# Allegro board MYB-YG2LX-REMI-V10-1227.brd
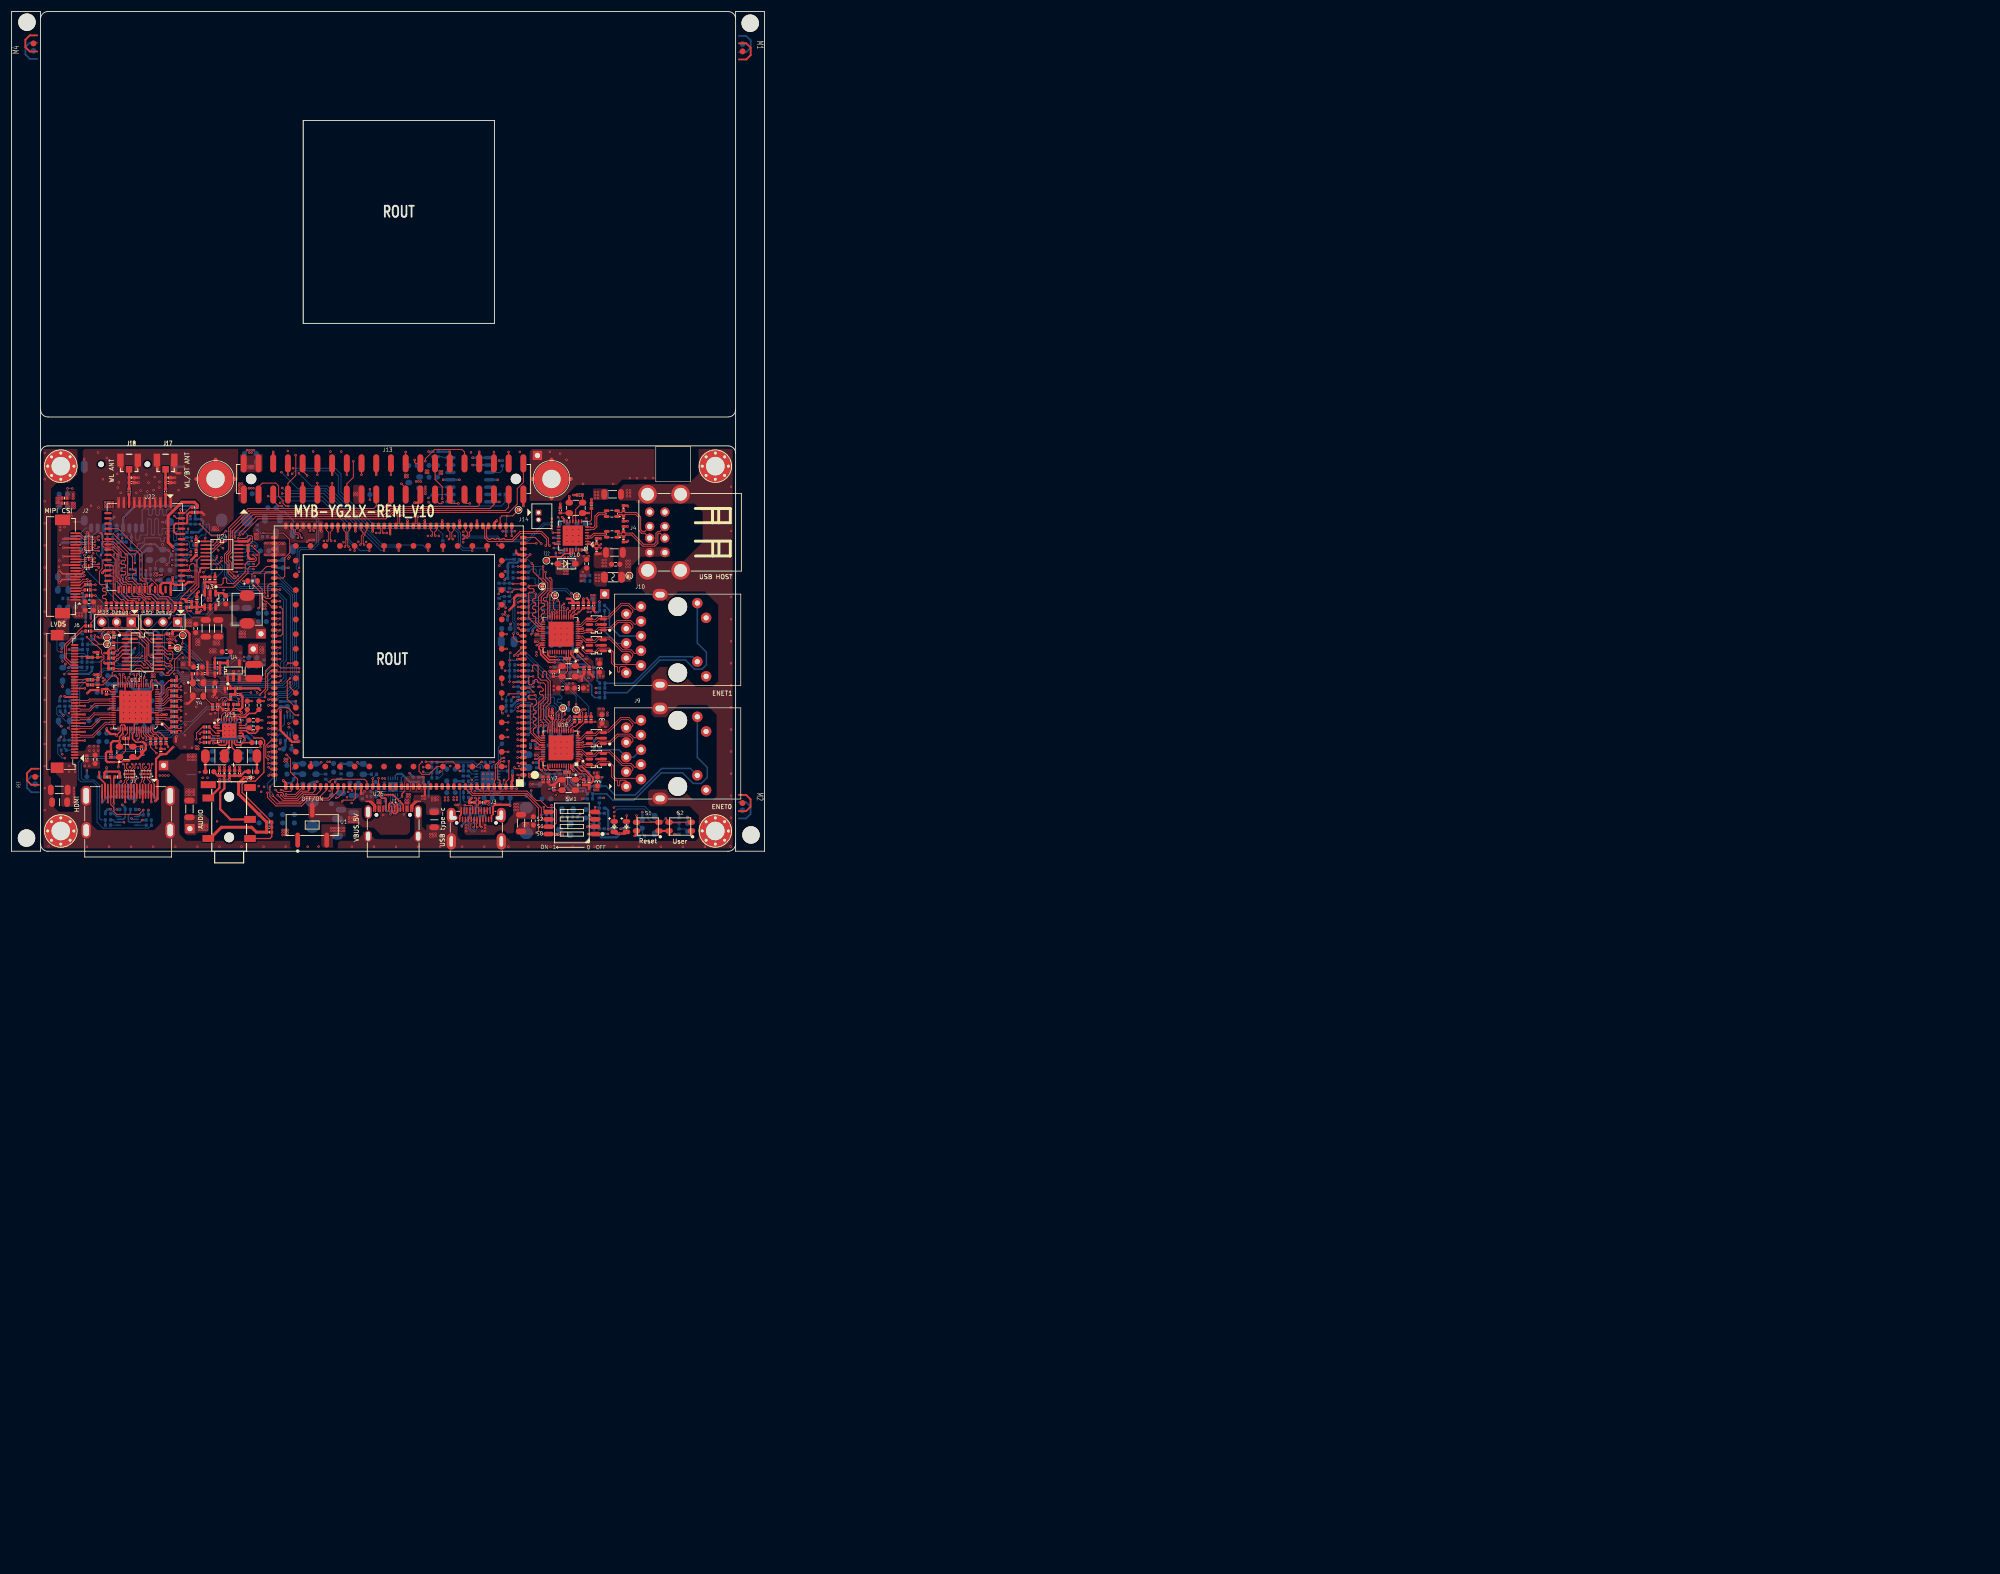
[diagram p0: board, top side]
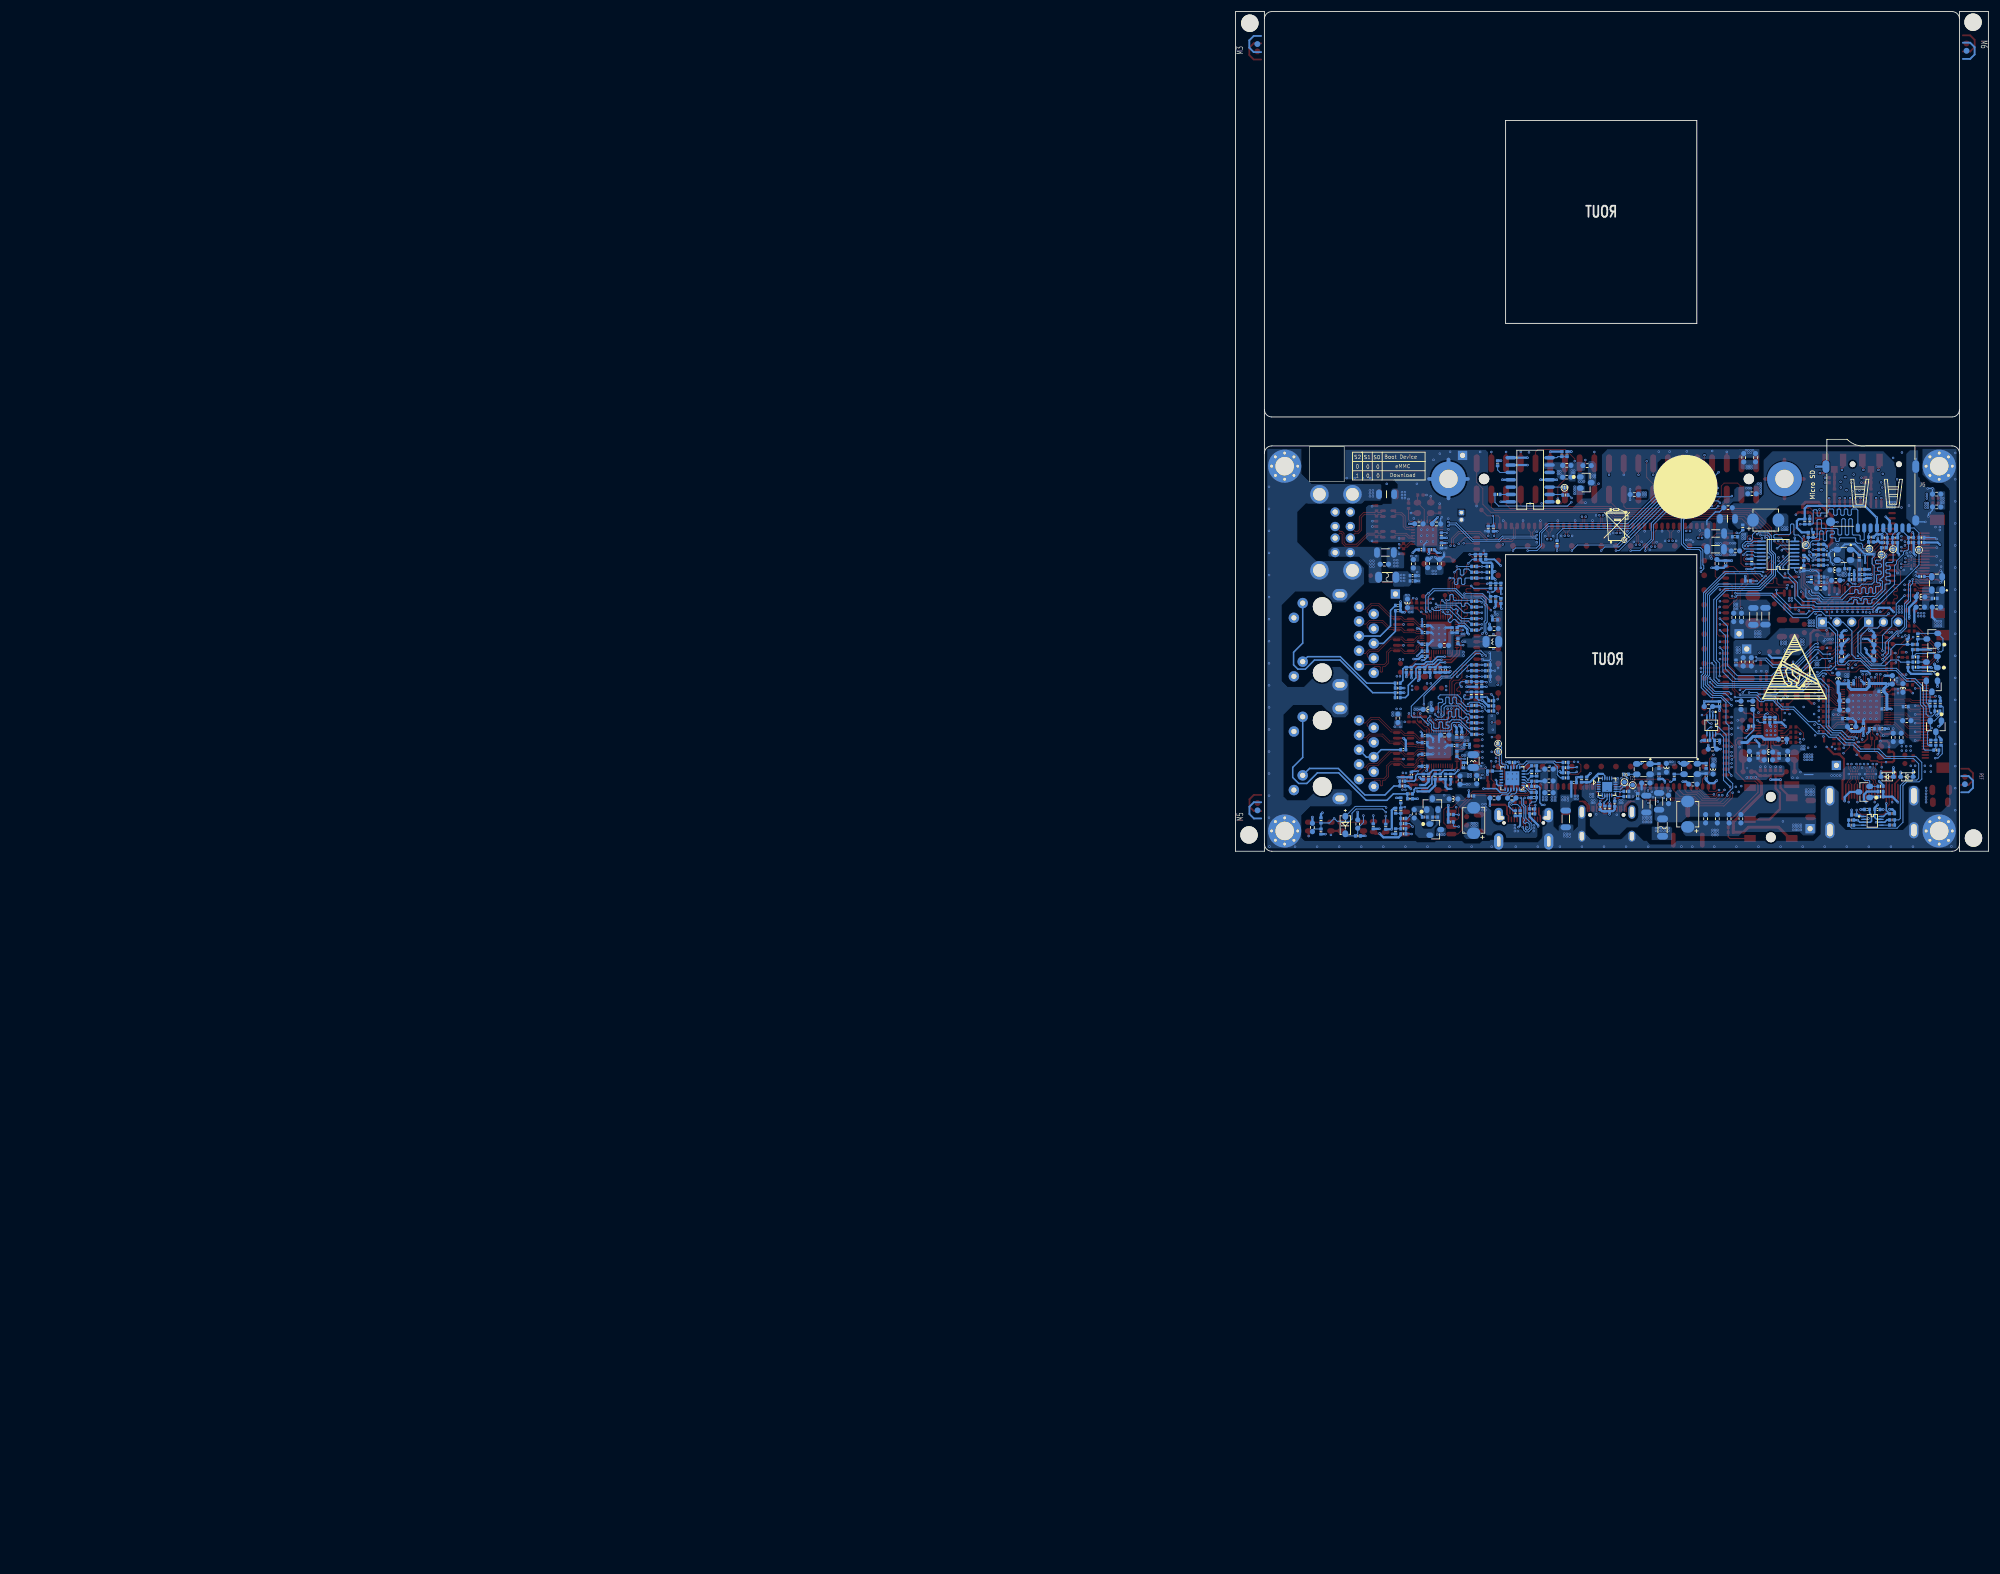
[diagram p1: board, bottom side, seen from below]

Outline 130 x 145 mm; copper layers: TOP, GND02, ART03, ART04, POW05, BOTTOM. Coordinates in mm from the lower left corner of the outline.
Outline path: 5,143.73 5,145 0,145 0,0 5,0 5,1.27 ; 5,143.73 5,76.27 ; 5,143.73 arc(5.37,144.63) 6.27,145 123.73,145 arc(124.63,144.63) 125,143.73 ; 5,76.27 5,68.73 ; 5,76.27 arc(5.37,75.37) 6.27,75 123.73,75 arc(124.63,75.37) 125,76.27 ; 5,68.73 arc(5.37,69.63) 6.27,70 123.73,70 arc(124.63,69.63) 125,68.73 ; 5,68.73 5,1.27 ; 5,1.27 arc(5.37,0.37) 6.27,0 123.73,0 arc(124.63,0.37) 125,1.27 ; 50.34,126.21 83.36,126.21 ; 50.34,126.21 83.36,126.21 ; 50.34,126.21 50.34,91.15 ; 50.34,126.21 50.34,91.15 ; 83.36,126.21 83.36,91.15 ; 83.36,126.21 83.36,91.15 ; 50.34,91.15 83.36,91.15 ; 50.34,91.15 83.36,91.15 ; 50.34,51.21 83.36,51.21 ; 50.34,51.21 83.36,51.21 ; 50.34,51.21 50.34,16.15 ; 50.34,51.21 50.34,16.15 ; 83.36,51.21 83.36,16.15 ; 83.36,51.21 83.36,16.15 ; 50.34,16.15 83.36,16.15 ; 50.34,16.15 83.36,16.15 ; 125,143.73 125,145 130,145 130,0 125,0 125,1.27 ; 125,143.73 125,76.27 ; 125,68.73 125,76.27 ; 125,68.73 125,1.27

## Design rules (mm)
net group AUDIO_MCLK: nets AUDIO_MCLK N26081482
net group DIFFPAIR0: nets RZ_USB0_DM RZ_USB0_DP
net group DIFFPAIR1: nets N26155524 N26155536
net group DIFFPAIR2: nets N26155544 N26155546
net group DPCSI_CLK_: nets CSI_CLK_N CSI_CLK_P
net group DPCSI_DATA0_: nets CSI_DATA0_N CSI_DATA0_P
net group DPCSI_DATA1_: nets CSI_DATA1_N CSI_DATA1_P
net group DPCSI_DATA2_: nets CSI_DATA2_N CSI_DATA2_P
net group DPCSI_DATA3_: nets CSI_DATA3_N CSI_DATA3_P
net group ET0_LINKSTA: nets ET0_LINKSTA N26048526
net group ET0_RX_CTL: nets ET0_RX_CTL N24791040
net group ET0_RXC: nets ET0_RXC N24696137
net group ET0_RXD0: nets ET0_RXD0 N24696102
net group ET0_RXD1: nets ET0_RXD1 N24696123
net group ET0_RXD2: nets ET0_RXD2 N24696121
net group ET0_RXD3: nets ET0_RXD3 N24696119
net group ET0_TX_CTL: nets ET0_TX_CTL N24790962
net group ET0_TXC: nets ET0_TXC N24696861
net group ET0_TXD1: nets ET0_TXD1 N24696875
net group ET0_TXD2: nets ET0_TXD2 N24696883
net group ET0_TXD3: nets ET0_TXD3 N24696881
net group ET1_RX_CTL: nets ET1_RX_CTL N24806933
net group ET1_RXD0: nets ET1_RXD0 N24807160
net group ET1_TX_CTL: nets ET1_TX_CTL N24806931
net group ET1_TXD0: nets ET1_TXD0 N24807847
net group ET1_TXD1: nets ET1_TXD1 N24807859
net group ET1_TXD2: nets ET1_TXD2 N24807879
net group ET1_TXD3: nets ET1_TXD3 N24807877
net group HOST1_USB: nets HOST1_USB_DM HOST1_USB_DP
net group HOST2_USB: nets HOST2_USB_DM HOST2_USB_DP
net group HPD_DET: nets HPD_DET N24681971
net group INT: nets INT RZ_P16_1_1V8
net group N23726017: nets N23726017 N23737816
net group N24759067: nets N24759067 N24761427
net group N24806528: nets N24806528 N24806541
net group RZ_DSI_CLK_N: nets N25318611 RZ_DSI_CLK_N
net group RZ_DSI_DATA0_N: nets N25318514 RZ_DSI_DATA0_N
net group RZ_DSI_DATA2_P: nets N25318630 RZ_DSI_DATA2_P
net group RZ_DSI_DATA3_N: nets N25318677 RZ_DSI_DATA3_N
net group RZ_P39_0_1V8: nets N23565746 RZ_P39_0_1V8
net group RZ_P42_2_1V8: nets N25318354 RZ_P42_2_1V8
net group RZ_P42_3: nets N25931062 RZ_P42_3
net group RZ_P43_0: nets N25931049 RZ_P43_0
net group RZ_P44_3: nets RZ_P44_2 RZ_P44_3
net group RZ_P48_2: nets N25931057 RZ_P48_2
net group RZ_SCIF1_CTS: nets RZ_SCIF1_CTS UART_CTS
net group RZ_SCIF1_RTS: nets RZ_SCIF1_RTS UART_RTS
net group RZ_SCIF1_RXD: nets N26045131 RZ_SCIF1_RXD
net group RZ_SCIF1_TXD: nets N26045129 RZ_SCIF1_TXD
net group RZ_SSI0_BCK: nets N26048225 RZ_SSI0_BCK
net group RZ_SSI0_RCK: nets N26048227 RZ_SSI0_RCK
net group RZ_SSI0_RXD: nets N26048711 RZ_SSI0_RXD
net group RZ_SSI0_TXD: nets N26048728 RZ_SSI0_TXD
net group RZ_USB1: nets RZ_USB1_DM RZ_USB1_DP
net group SDIO_CLK: nets SDIO_CLK WIFI_SD1_CLK
net group SDIO_CMD: nets SDIO_CMD WIFI_SD1_CMD
net group SDIO_DATA0: nets SDIO_DATA0 WIFI_SD1_D0
net group SDIO_DATA1: nets SDIO_DATA1 WIFI_SD1_D1
net group SDIO_DATA2: nets SDIO_DATA2 WIFI_SD1_D2
net group SDIO_DATA3: nets SDIO_DATA3 WIFI_SD1_D3
net group TX0__OUT: nets TX0_DN_OUT TX0_DP_OUT
net group TX1_OUT: nets TX1_DN_OUT TX1_DP_OUT
net group TX2_OUT: nets TX2_DN_OUT TX2_DP_OUT
net group TX_CK_OUT: nets TX_CKN_OUT TX_CKP_OUT
net group CARRIER_PWR_ON: nets CARRIER_PWR_ON N26033210 N26043190
net group DPTX: nets TX0_DN TX0_DP TX1_DN TX1_DP TX2_DN TX2_DP TX_CKN TX_CKP
net group ET1_RXD1: nets N24807181
net group ET1_RXD2: nets N24807179
net group ET1_RXD3: nets N24807177
net group ET1_TXC: nets ET1_TXC
net group LVDS: nets LVDS_CLK+ LVDS_CLK- LVDS_D0+ LVDS_D0- LVDS_D1+ LVDS_D1- LVDS_D2+ LVDS_D2- LVDS_D3+ LVDS_D3-
net group RGB: nets RZ_DISP_CLK RZ_DISP_DATA2 RZ_DISP_DATA5 RZ_DISP_DATA10 RZ_DISP_DATA11 RZ_DISP_DATA12 RZ_DISP_DATA13 RZ_DISP_DATA14 RZ_DISP_DATA15 RZ_DISP_DATA16 RZ_DISP_DATA17 RZ_DISP_DATA18 RZ_DISP_DATA19 RZ_DISP_DATA21 RZ_DISP_DE RZ_DISP_HSYNC RZ_DISP_VSYNC
net group RIIC0_SCL_1V8: nets N23563890 N25318324 RIIC0_SCL_1V8
net group RIIC0_SDA_1V8: nets N23563869 N25318297 RIIC0_SDA_1V8
net group RZ_CSI_DATA: nets RZ_CSI_CLK_N RZ_CSI_CLK_P RZ_CSI_DATA0_N RZ_CSI_DATA0_P RZ_CSI_DATA1_N RZ_CSI_DATA1_P RZ_CSI_DATA2_N RZ_CSI_DATA2_P RZ_CSI_DATA3_N RZ_CSI_DATA3_P
net group RZ_P43_3: nets RZ_P43_3
net group RZ_RIIC0_SCL: nets N25931055 N26059408 RZ_RIIC0_SCL
net group RZ_RIIC0_SDA: nets N25931053 N26059410 RZ_RIIC0_SDA
net group RZ_RIIC1_SCL: nets N23950839 N24683528 N26048238 RZ_RIIC1_SCL
net group RZ_RIIC1_SDA: nets N23950837 N24683530 N26048236 RZ_RIIC1_SDA
net group SD1_CLK: nets N24944194
net group USB2CC1: nets N26059354 N26059432 USB2CC1
net group USB2CC2: nets N26059364 N26059430 USB2CC2

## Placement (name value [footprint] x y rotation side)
C1  22uF/12/25V  [C1206]  59.05 8.15 90 bottom
C2  10nF/4/50V  [C0402]  60.55 9.53 90 bottom
C3  22uF/12/25V  [C1206]  56.86 8.61 90 bottom
C4  100nF/6/50V  [C0603]  55.23 8.94 90 bottom
C5  100nF/6/50V  [C0603]  46.8 5.62 270 bottom
C6  100nF/6/50V  [C0603]  48.83 5.62 270 bottom
C7  1uF/6/25V  [C0603]  44.77 5.62 270 bottom
C8  100nF/6/50V  [C0603]  42.73 5.62 270 bottom
C9  22uF/12/25V  [C1206]  30.7 7.32 270 top
C12  100nF/4/16V  [C0402]  30.65 43.12 180 top
C13  1uF/4/6.3V  [C0402]  71.57 11.88 0 bottom
C14  1nF/12/2kV  [C1206]  72.97 5.59 270 bottom
C15  22uF/12/25V  [C1206]  35.66 38.5 270 top
C16  22uF/12/25V  [C1206]  33.52 38.5 270 top
C17  100nF/6/50V  [C0603]  31.78 38.47 270 top
C18  100nF/6/50V  [C0603]  36.97 43.42 270 top
C19  1nF/4/50V  [C0402]  33.34 46.93 270 top
C20  DNP  [C1206]  40.59 40.56 90 bottom
C21  100nF/6/50V  [C0603]  42.63 40.39 90 bottom
C22  22uF/12/25V  [C1206]  38.5 40.59 90 bottom
C23  100nF/6/50V  [C0603]  43.98 40.39 90 bottom
C24  68pF/4/50V  [C0402]  35.53 31.66 180 top
C25  22uF/6/6.3V  [C0603]  42.34 32.71 270 bottom
C26  22uF/6/6.3V  [C0603]  40.94 32.71 270 bottom
C27  100nF/4/16V  [C0402]  43.58 32.59 270 bottom
C28  22uF/6/6.3V  [C0603]  37.07 34.46 180 top
C29  100nF/6/50V  [C0603]  11.76 42.15 0 bottom
C30  100nF/6/50V  [C0603]  8.97 42.15 0 bottom
C31  10uF/6/16V  [C0603]  13.41 41.62 0 top
C32  100nF/6/50V  [C0603]  13.41 43.06 0 top
C33  100nF/6/50V  [C0603]  25.35 33.63 270 bottom
C34  1uF/6/25V  [C0603]  25.35 36.37 90 bottom
C35  100nF/6/50V  [C0603]  19.75 36.37 90 bottom
C36  1uF/6/25V  [C0603]  19.78 33.74 270 bottom
C37  100nF/4/16V  [C0402]  46.42 25.43 90 bottom
C38  1uF/6/25V  [C0603]  48.34 24.99 0 bottom
C39  100nF/4/16V  [C0402]  46.83 19.15 180 bottom
C40  1uF/6/25V  [C0603]  47.65 17.64 0 bottom
C41  10uF/6/16V  [C0603]  75.87 14.18 180 bottom
C42  100nF/6/50V  [C0603]  75.87 12.15 180 bottom
C43  100nF/6/50V  [C0603]  99.14 6.46 270 bottom
C44  100nF/6/50V  [C0603]  90.09 5.24 270 top
C45  47uF/12/10V  [C1206]  87.96 4.88 270 top
C46  10uF/6/16V  [C0603]  75.87 10.12 180 bottom
C47  1nF/4/50V  [C0402]  78.46 9.27 0 bottom
C48  1nF/4/50V  [C0402]  77.99 13.42 90 bottom
C49  10uF/6/16V  [C0603]  85.34 9.19 0 bottom
C50  10uF/6/16V  [C0603]  82.29 9.19 180 bottom
C51  47uF/12/10V  [C1206]  104.06 51.59 180 top
C52  100nF/6/50V  [C0603]  104.29 49.56 180 bottom
C53  100nF/6/50V  [C0603]  104.29 49.56 180 top
C54  47uF/12/10V  [C1206]  104.11 51.59 180 bottom
C55  1nF/12/2kV  [C1206]  103.76 61.65 0 top
C56  10uF/6/16V  [C0603]  96.82 49.68 90 bottom
C57  1uF/6/25V  [C0603]  94.79 49.68 90 bottom
C58  100nF/4/16V  [C0402]  99.41 46.69 180 bottom
C59  100nF/4/16V  [C0402]  99.41 47.6 180 bottom
C60  10uF/6/16V  [C0603]  95.3 56.53 180 bottom
C61  1uF/6/25V  [C0603]  98.32 56.54 180 bottom
C62  100nF/4/16V  [C0402]  97.91 52.08 180 bottom
C63  100nF/4/16V  [C0402]  94.45 52.79 270 bottom
C64  22pF/4/50V  [C0402]  98.09 61.52 180 top
C65  22pF/4/50V  [C0402]  94.74 58.88 90 top
C66  10uF/6/16V  [C0603]  8.94 59.46 0 bottom
C67  100nF/6/50V  [C0603]  8.94 61.67 0 bottom
C68  100nF/4/16V  [C0402]  12.99 16.05 270 top
C69  10uF/6/16V  [C0603]  14.42 15.88 270 top
C70  33pF/4/50V  [C0402]  22.45 17.63 270 top
C71  33pF/4/50V  [C0402]  17.15 16.71 90 top
C72  3.3nF/4/50V  [C0402]  16.38 27.56 90 top
C73  10uF/6/16V  [C0603]  16.58 29.59 90 bottom
C74  100nF/4/16V  [C0402]  21.02 28.97 0 bottom
C75  100nF/4/16V  [C0402]  24.74 22.91 180 bottom
C76  100nF/4/16V  [C0402]  17.97 24.59 0 bottom
C77  10uF/6/16V  [C0603]  23.62 21.51 180 bottom
C78  100nF/4/16V  [C0402]  23.7 28.92 180 bottom
C79  10uF/6/16V  [C0603]  24.96 25.98 180 bottom
C80  100nF/4/16V  [C0402]  21.58 21.61 90 bottom
C81  1nF/12/2kV  [C1206]  8.23 10.59 0 top
C82  10uF/6/16V  [C0603]  15.06 19.66 270 bottom
C83  100nF/4/16V  [C0402]  14.28 24.97 180 bottom
C84  10uF/6/16V  [C0603]  16.43 19.66 270 bottom
C85  100nF/4/16V  [C0402]  18.34 21.17 180 bottom
C86  10uF/6/16V  [C0603]  24.96 24.38 180 bottom
C87  100nF/4/16V  [C0402]  18.49 27.62 0 bottom
C88  10uF/6/16V  [C0603]  14.09 22.56 180 bottom
C89  100nF/4/16V  [C0402]  20.12 21.17 0 bottom
C90  100nF/4/16V  [C0402]  20.95 7.21 0 bottom
C91  100nF/4/16V  [C0402]  19.17 7.21 180 bottom
C92  10uF/6/16V  [C0603]  35.1 28.37 270 top
C93  100nF/4/16V  [C0402]  33.36 30.67 0 top
C94  33pF/4/50V  [C0402]  35.58 24.92 90 top
C95  33pF/4/50V  [C0402]  36.98 24.46 180 top
C96  33pF/4/50V  [C0402]  38.76 24.46 0 top
C97  1nF/4/50V  [C0402]  39.36 13.47 90 top
C98  1nF/4/50V  [C0402]  35.89 13.47 90 top
C99  1uF/6/25V  [C0603]  42.72 25.21 270 top
C100  1uF/6/25V  [C0603]  40.69 25.21 270 top
C101  10uF/6/16V  [C0603]  41.26 16.54 270 bottom
C102  100nF/4/16V  [C0402]  39.77 16.49 270 bottom
C103  100nF/4/16V  [C0402]  36.14 16.46 270 bottom
C104  10uF/6/16V  [C0603]  34.65 16.54 270 bottom
C105  1nF/4/50V  [C0402]  44.47 4.15 180 top
C106  10uF/6/16V  [C0603]  35.54 19.35 0 bottom
C107  10uF/6/16V  [C0603]  41.75 21.31 0 top
C108  10uF/6/16V  [C0603]  41.75 22.63 0 top
C109  10uF/6/16V  [C0603]  51.02 11.58 0 bottom
C110  100nF/4/16V  [C0402]  48.72 12.98 270 bottom
C111  10uF/6/16V  [C0603]  59.14 11.78 0 bottom
C112  100nF/4/16V  [C0402]  56.88 12.93 270 bottom
C113  4.7uF/6/16V  [C0603]  91.22 12.28 270 bottom
C114  100nF/4/16V  [C0402]  92.65 12.41 270 top
C115  100nF/4/16V  [C0402]  91.76 12.41 270 top
C116  4.7uF/6/16V  [C0603]  101.95 22.96 90 bottom
C117  100nF/4/16V  [C0402]  92.19 18.28 0 bottom
C118  100nF/4/16V  [C0402]  90.03 18.45 180 bottom
C119  100nF/4/16V  [C0402]  97.32 19.96 180 bottom
C120  100nF/4/16V  [C0402]  99.63 13.22 270 bottom
C121  27pF/4/50V  [C0402]  93.62 11 270 top
C122  4.7uF/6/16V  [C0603]  88.36 12.37 270 bottom
C123  100nF/4/16V  [C0402]  90.65 14.86 90 bottom
C124  100nF/4/16V  [C0402]  93.36 23.43 90 top
C125  100nF/4/16V  [C0402]  97.32 16.76 180 bottom
C126  100nF/4/16V  [C0402]  97.32 18.76 180 bottom
C127  100nF/4/16V  [C0402]  97.32 14.67 0 bottom
C128  27pF/4/50V  [C0402]  98.81 11.91 270 top
C129  100nF/4/16V  [C0402]  101.02 17.55 180 bottom
C130  4.7uF/6/16V  [C0603]  93.87 20.05 0 bottom
C131  100nF/4/16V  [C0402]  90.92 20.12 90 bottom
C132  4.7uF/6/16V  [C0603]  95.15 28.17 180 top
C133  100nF/4/16V  [C0402]  93.76 31.33 270 bottom
C134  100nF/4/16V  [C0402]  94.65 31.33 270 bottom
C135  100nF/4/16V  [C0402]  97.32 38.96 180 bottom
C136  100nF/4/16V  [C0402]  97.32 34.56 180 bottom
C137  27pF/4/50V  [C0402]  93.54 30.63 270 top
C138  4.7uF/6/16V  [C0603]  85.34 38.45 0 bottom
C139  100nF/4/16V  [C0402]  85.19 39.95 0 bottom
C140  100nF/4/16V  [C0402]  101.94 41.55 180 bottom
C141  100nF/4/16V  [C0402]  101.94 42.44 180 bottom
C142  100nF/4/16V  [C0402]  100.5 42.44 270 top
C143  100nF/4/16V  [C0402]  97.32 35.76 180 bottom
C144  100nF/4/16V  [C0402]  97.32 37.76 180 bottom
C145  100nF/4/16V  [C0402]  97.32 33.67 0 bottom
C146  27pF/4/50V  [C0402]  98.84 31.37 90 top
C147  4.7uF/6/16V  [C0603]  93.92 35.54 0 bottom
C148  100nF/4/16V  [C0402]  92.6 38.18 90 bottom
C149  DNP  [C0402]  20.73 63.66 0 top
C150  33pF/4/50V  [C0402]  20.29 62.1 90 top
C151  33pF/4/50V  [C0402]  26.59 62.1 90 top
C152  DNP  [C0402]  27.03 63.66 0 top
C153  100nF/4/16V  [C0402]  28.83 46.46 0 bottom
C154  10uF/6/16V  [C0603]  26.36 46.79 180 bottom
C155  100nF/4/16V  [C0402]  28.83 47.35 0 bottom
C156  10uF/6/16V  [C0603]  28.95 45.42 0 bottom
C157  DNP  [C0402]  21.84 47.79 180 bottom
C158  DNP  [C0402]  23.61 47.79 180 bottom
C159  100nF/6/50V  [C0603]  108.89 4.7 90 bottom
C160  10uF/6/16V  [C0603]  61.14 61.6 0 bottom
C161  1uF/6/25V  [C0603]  40.82 61.74 0 bottom
C162  10uF/6/16V  [C0603]  40.21 67.96 90 bottom
C163  1uF/6/25V  [C0603]  42.25 67.96 90 bottom
C164  100nF/6/50V  [C0603]  116.71 4.11 90 bottom
C165  10uF/6/16V  [C0603]  72.79 64.59 180 bottom
C166  100nF/6/50V  [C0603]  72.79 66.63 180 bottom
C167  DNP  [C0603]  69.29 66.6 0 bottom
C168  10uF/6/16V  [C0603]  43.68 51.87 180 bottom
C169  100nF/4/16V  [C0402]  43.76 54.32 180 bottom
C170  47uF/12/10V  [C1206]  47.11 52.16 0 bottom
C171  47uF/12/10V  [C1206]  47.09 54.88 0 bottom
C172  22uF/6/16V  [C0603]  44.95 59.33 0 bottom
C173  4.7uF/6/16V  [C0603]  46.88 49.66 270 bottom
C174  100nF/4/16V  [C0402]  45.35 49.74 270 bottom
C176  1uF/6/25V  [C0603]  99.28 49.64 270 top
C177  10uF/6/16V  [C0603]  99.28 49.64 270 bottom
C178  100nF/4/16V  [C0402]  39.06 27.08 0 top
CT1  47uF/3528/10V  [CT3528-B]  40.71 16.43 0 top
CT2  47uF/3528/10V  [CT3528-B]  35.11 16.43 180 top
D1  SMBJ6.0CA  [DO-214AA]  51.91 6.4 90 bottom
D2  B72590D50H160  [D0402]  67.03 7.65 90 bottom
D3  B72590D50H160  [D0402]  64.51 8.2 90 bottom
D4  B72590D50H160  [D0402]  65.41 7.36 90 bottom
D5  B72590D50H160  [D0402]  66.21 7.36 90 bottom
D6  SMBJ6.0CA  [DO-214AA]  88.86 5.32 90 bottom
D7  B72590D50H160  [D0402]  81.28 8.43 180 top
D8  B72590D50H160  [D0402]  79.48 8.43 0 top
D9  B72590D50H160  [D0402]  78.76 6.47 180 bottom
D10  B72590D50H160  [D0402]  81.68 6.56 270 bottom
D11  B72590D50H160  [D0402]  105.64 57.45 90 top
D12  B72590D50H160  [D0402]  105.64 59.25 270 top
D13  B72590D50H160  [D0402]  105.64 55.65 270 top
D14  B72590D50H160  [D0402]  105.64 53.85 90 top
D15  B72590D50H160  [D0402]  100.99 51.79 90 top
D16  B72590D50H160  [D0402]  100.99 53.59 270 top
D17  LMBR140T1G  [SOD123]  95.81 49.65 0 top
D18  B72590D50H160  [D0402]  30.86 56.93 270 bottom
D19  B72590D50H160  [D0402]  30.25 54.62 270 bottom
D20  B72590D50H160  [D0402]  20.26 54.25 0 bottom
D21  B72590D50H160  [D0402]  17.9 54.15 180 bottom
D22  B72590D50H160  [D0402]  16.1 54.15 0 bottom
D23  B72590D50H160  [D0402]  13.36 54.16 0 bottom
D24  B72590D50H160  [D0402]  11.56 54.16 0 bottom
D25  RB751V40,115  [SOD323]  14.07 12.85 180 bottom
D26  RB751V40,115  [SOD323]  17.47 12.85 180 bottom
D27  B72590D50H160  [D0402]  37.63 13.48 270 top
D28  B72590D50H160  [D0402]  36.74 13.48 270 top
D29  B72590D50H160  [D0402]  44.48 3.31 0 top
D30  B72590D50H160  [D0402]  99.87 9.07 0 bottom
D31  B72590D50H160  [D0402]  101.19 11.26 0 bottom
D32  B72590D50H160  [D0402]  101.98 27.38 0 bottom
D33  B72590D50H160  [D0402]  101.98 28.18 0 bottom
D34  B72590D50H160  [D0402]  20.73 64.51 180 top
D35  B72590D50H160  [D0402]  27.03 64.51 180 top
D36  LMBR120FT1G  [SOD123]  111.03 4.52 270 bottom
D37  B72590D50H160  [D0402]  108.85 2.65 0 bottom
D38  B72590D50H160  [D0402]  115.24 3.4 90 bottom
D39  Red  [LED0805]  106.16 4.25 0 top
D40  LBAT54CLT1G  [SOT-23]  69.47 63.67 270 bottom
D41  Red  [LED0805]  104.04 4.24 0 top
D42  Blue  [LED0603]  41.6 46.67 0 top
D43  B72590D50H160  [D0402]  9 17.46 0 bottom
D44  B72590D50H160  [D0402]  8.82 24.2 0 bottom
D45  B72590D50H160  [D0402]  13.88 32.22 90 bottom
D46  B72590D50H160  [D0402]  13.98 36.17 270 bottom
D47  SMBJ6.0CA  [DO-214AA]  38.45 57.18 180 bottom
F1  4A/72V  [F1206]  56.26 4.1 90 bottom
F2  SMD1206-050-16V  [F1206]  103.78 47.32 0 bottom
F3  SMD1206-050-16V  [F1206]  103.83 47.32 180 top
FB1  220R/1.5A  [FB0603]  11.72 43.92 0 bottom
FB2  220R/1.5A  [FB0603]  92.35 9.04 180 bottom
FB3  220R/1.5A  [FB0603]  25.93 29.87 90 bottom
FB4  220R/1.5A  [FB0603]  14.77 28.2 90 bottom
FB5  220R/1.5A  [FB0603]  32.18 31.83 0 top
FB6  220R/1.5A  [FB0603]  38 17.14 0 bottom
FB7  220R/1.5A  [FB0603]  47.54 14.08 270 bottom
FB8  220R/1.5A  [FB0603]  55.6 14.41 270 bottom
FB9  220R/1.5A  [FB0603]  101.92 22.81 90 top
FB10  220R/1.5A  [FB0603]  101.15 12.06 90 top
FB11  220R/1.5A  [FB0603]  96.85 24.48 0 bottom
FB12  220R/1.5A  [FB0603]  97.96 28.18 0 top
FB13  220R/1.5A  [FB0603]  101.51 31.67 90 top
FB14  220R/1.5A  [FB0603]  100.3 42.8 270 bottom
FB15  220R/1.5A  [FB0603]  26.6 48.56 0 bottom
J1  BTCR-16-307  [TYPE-C-BTCF-16-307]  65.88 2.68 0 top
J2  FPC05024-17205  [FPC24-0_5-H]  11.22 49.17 270 top
J3  -  [UT12111-B1609-7F]  80.23 2.9 0 top
J4  -  [UB11121-8FDE-4F]  117 55.08 270 top
J5  -  [WQ21801-B2180-7F]  20.3 63.73 0 bottom
J6  FPC05040-17205  [FPC40-0_5-H]  8.59 25.87 270 top
J7  QJ51191-LFB4-7F  [QJ51191-LFB4]  20.13 6.61 0 top
J8  704-06700003-A  [CKX-704]  37.56 5.9 90 top
J9  -  [S11-ZZ-0319]  115.01 16.89 90 top
J10  -  [S11-ZZ-0319]  115.01 36.53 90 top
J13  1125-1220S1M111CR0  [TSM-2D54-2X20P]  64.22 64.29 0 top
J14  530470210  [CONN1X2-1_25-DIP]  90.98 57.86 90 top
J15  1X3PIN-2_54  [CONN1X3-2_54-DIP]  26.13 39.58 270 top
J16  1X3PIN-2_54  [CONN1X3-2_54-DIP]  18.13 39.58 270 top
J17  U.FL-R-SMT-1(01)  [FL_2D95X1D55_2SP]  26.59 67.56 0 top
J18  U.FL-R-SMT-1(01)  [FL_2D95X1D55_2SP]  20.29 67.56 0 top
L2  2.2uH/35mR/5.5A  [L5_2X5_5]  40.66 41.74 0 top
L3  2.2uH  [L3X3]  41.83 31.05 180 top
L4  90ohm/280mA  [INDCM-SDCW2012]  103.63 58.3 180 top
L5  90ohm/280mA  [INDCM-SDCW2012]  103.66 54.73 180 top
L6  2.2uH/80mohm/0.85A  [L2X2_5]  88.95 15.57 270 bottom
L7  2.2uH/80mohm/0.85A  [L2X2_5]  85.64 36.2 180 bottom
M1  Mark Piont  [ID-BOARD]  126.21 138.13 270 top
M2  Mark Piont  [ID-BOARD]  126.18 8.33 270 top
M3  Mark Piont  [ID-BOARD]  126.21 139.4 90 bottom
M4  Mark Piont  [ID-BOARD]  3.78 139.5 90 top
M5  Mark Piont  [ID-BOARD]  126.18 7.06 90 bottom
M6  Mark Piont  [ID-BOARD]  3.78 138.23 270 bottom
MTG1  MHOLE  [HOLE3_2P-8]  8.5 66.5 0 top
MTG2  MHOLE  [HOLE3_2P-8]  121.5 66.5 0 top
MTG3  MHOLE  [HOLE3_2P-8]  121.5 3.5 0 top
MTG4  MHOLE  [HOLE3_2P-8]  8.5 3.5 180 top
MTG5  -  [MH236-125T]  35.22 64.29 0 top
MTG6  -  [MH236-125T]  93.22 64.29 180 top
NOREF  -  []  466.54 84.05 0 top
NOREF#2  -  []  441.63 144.78 0 top
NOREF#3  -  [unnamed#3]  127.52 142.99 90 top
NOREF#4  -  []  0 0 90 top
NOREF#5  -  []  467.08 8.51 0 top
NOREF#6  -  []  0 0 0 top
NOREF#7  -  [unnamed#3]  2.58 2.27 270 top
NOREF#8  -  []  435.48 -46.51 0 top
NOREF#9  -  []  -6.96 24.16 0 top
NOREF#10  -  [unnamed#3]  2.65 143.17 270 top
NOREF#11  -  []  5 0 90 top
NOREF#12  -  [unnamed#3]  127.66 2.82 270 top
NOREF#13  -  []  435.12 -1.35 0 top
NOREF#14  -  []  5 70 0 top
NOREF#15  -  []  61.62 56.31 180 bottom
NOREF#16  -  []  52.32 62.79 0 bottom
NOREF#17  -  []  33.88 31.42 180 bottom
Q3  YJL2305A  [SOT-23]  95.45 3.73 270 bottom
Q4  YJL2305A  [SOT-23]  96 8.18 180 bottom
Q5  LMBT3904LT1G  [SOT-23]  21.48 10.24 90 bottom
Q6  LBSS139LT1G  [SOT-23]  9.07 21.52 0 bottom
Q7  LBSS139LT1G  [SOT-23]  9.76 28.43 0 bottom
Q8  LBSS139LT1G  [SOT-23]  9.82 32.67 90 bottom
Q9  LBSS139LT1G  [SOT-23]  9.74 36.66 90 bottom
R3  0R/4/5%  [R0402]  70.25 12.37 90 bottom
R4  1M/12/5%  [R1206]  72.97 5.44 90 top
R5  5.1K/4/5%  [R0402]  62.51 10.34 0 bottom
R6  5.1K/4/5%  [R0402]  62.51 9.45 0 bottom
R8  0R/4/5%  [R0402]  37.8 26.65 90 top
R9  DNP  [R0402]  69.36 12.37 270 bottom
R10  DNP/10K  [R0402]  31.99 43.46 270 top
R11  200K/4/1%  [R0402]  34.23 46.93 270 top
R12  DNP/10K  [R0402]  31.99 41.68 270 top
R14  44.2K/4/1%  [R0402]  35.12 46.93 90 top
R15  0R/4/5%  [R0402]  30.66 42.13 0 top
R16  DNP  [R0402]  39.06 28.14 180 top
R17  20K/4/1%  [R0402]  35.53 32.55 180 top
R18  DNP  [R0402]  37.28 28.14 180 top
R19  10K/4/1%  [R0402]  35.53 30.77 180 top
R20  10K/4/5%  [R0402]  9.29 43.66 180 bottom
R21  22R/4/5%  [R0402]  11.53 47.45 0 bottom
R23  22R/4/5%  [R0402]  13.41 44.16 180 top
R24  22R/4/5%  [R0402]  13.11 45.13 180 top
R25  22R/4/5%  [R0402]  13.18 46.02 180 top
R26  10K/4/5%  [R0402]  17.18 31.56 0 top
R27  2.2K/4/5%  [R0402]  17.62 37.34 270 top
R28  2.2K/4/5%  [R0402]  17.62 35.56 90 top
R29  10K/4/5%  [R0402]  17.18 34.23 0 top
R30  DNP  [R0402]  17.18 33.34 0 top
R31  DNP  [R0402]  17.18 32.45 0 top
R32  DNP  [R0402]  27.33 37.54 180 top
R33  DNP  [R0402]  27.3 35.56 90 top
R34  10K/4/5%  [R0402]  48.54 19.15 180 bottom
R35  DNP  [R0402]  89.28 9.55 180 bottom
R36  10K/4/5%  [R0402]  95.53 5.91 0 bottom
R37  1K/4/5%  [R0402]  97.3 5.91 0 bottom
R38  10K/4/5%  [R0402]  78.43 12.09 0 bottom
R39  10K/4/5%  [R0402]  85.47 55.7 90 bottom
R40  0R/4/5%  [R0402]  78.46 10.16 180 bottom
R41  0R/4/5%  [R0402]  78.77 7.32 180 bottom
R42  0R/4/5%  [R0402]  80.83 6.57 270 bottom
R43  10K/4/5%  [R0402]  82.2 15.34 180 bottom
R44  DNP  [R0402]  73 13.56 180 bottom
R45  DNP  [R0402]  78.43 11.2 180 bottom
R46  DNP  [R0402]  73 14.45 180 bottom
R47  0R/4/5%  [R0402]  78.88 13.42 270 bottom
R48  DNP  [R0402]  86.36 55.7 270 bottom
R49  0R/4/5%  [R0402]  86.05 13.84 0 bottom
R50  22R/4/5%  [R0402]  73 15.34 180 bottom
R51  22R/4/5%  [R0402]  73 12.67 180 bottom
R52  10K/4/5%  [R0402]  78.43 14.76 180 bottom
R53  1M/12/5%  [R1206]  103.91 61.65 180 bottom
R54  4.7K/4/5%/DNP  [R0402]  94.45 54.57 90 bottom
R55  2.2K/4/5%/DNP  [R0402]  96.13 52.08 0 bottom
R56  0R/4/5%  [R0402]  102.35 7 90 bottom
R57  DNP  [R0402]  102.35 3.44 270 bottom
R58  DNP  [R0402]  101.01 3.89 180 bottom
R59  1K/4/5%  [R0402]  101.01 4.78 180 bottom
R60  1K/4/5%  [R0402]  101.01 5.66 180 bottom
R61  DNP  [R0402]  101.46 7 90 bottom
R62  1K/4/5%  [R0402]  101.01 3 0 bottom
R63  1K/4/5%  [R0402]  101.46 8.78 90 bottom
R64  DNP  [R0402]  92.82 5.05 0 bottom
R65  DNP  [R0402]  92.81 6.32 0 bottom
R66  DNP  [R0402]  9.14 60.99 0 top
R67  0R/4/5%  [R0402]  9.14 60.1 0 top
R68  10K/4/5%  [R0402]  31.71 56.92 270 bottom
R69  10K/4/5%  [R0402]  31.1 54.63 270 bottom
R70  10K/4/5%  [R0402]  20.27 53.4 0 bottom
R71  10K/4/5%  [R0402]  17.89 53.3 180 bottom
R72  10K/4/5%  [R0402]  16.11 53.3 0 bottom
R73  10K/4/5%  [R0402]  13.35 53.32 0 bottom
R74  10K/4/5%  [R0402]  11.57 53.32 0 bottom
R75  22R/4/5%  [R0402]  18.04 52.41 180 bottom
R76  1K/4/5%  [R0402]  25.78 17.22 90 top
R77  1M/4/5%  [R0402]  19.7 19.5 180 top
R78  0R/4/5%  [R0402]  24 19 90 top
R79  0R/4/5%  [R0402]  24.89 19 90 top
R80  0R/4/5%  [R0402]  25.78 19 90 top
R81  0R/4/5%  [R0402]  26.67 19 90 top
R82  0R/4/5%  [R0402]  28.06 21.49 0 top
R83  10K/4/5%  [R0402]  14.89 28.28 90 top
R84  10K/4/5%  [R0402]  14.89 30.06 270 top
R85  10K/4/5%  [R0402]  14.87 33.92 270 top
R86  0R/4/5%  [R0402]  13.56 28.73 180 top
R87  0R/4/5%  [R0402]  13.56 29.62 180 top
R88  0R/4/5%  [R0402]  28.06 20.6 0 top
R89  0R/4/5%  [R0402]  28.06 22.38 0 top
R90  0R/4/5%  [R0402]  28.06 23.27 0 top
R91  0R/4/5%  [R0402]  13.25 38.91 180 top
R92  0R/4/5%  [R0402]  13.25 38.02 180 top
R93  0R/4/5%  [R0402]  28.06 24.16 0 top
R94  0R/4/5%  [R0402]  13.53 33.48 180 top
R95  0R/4/5%  [R0402]  28.06 25.04 0 top
R96  0R/4/5%  [R0402]  28.06 25.93 0 top
R97  0R/4/5%  [R0402]  28.06 26.82 0 top
R98  0R/4/5%  [R0402]  28.06 27.71 0 top
R99  0R/4/5%  [R0402]  28.06 28.6 0 top
R100  6.04K/4/1%  [R0402]  28.06 29.49 180 top
R101  4.7K/4/5%  [R0402]  16.49 12.82 0 top
R102  4.7K/4/5%  [R0402]  18.26 12.82 180 top
R103  100K/4/5%  [R0402]  18.61 9.42 0 bottom
R104  1M/12/5%  [R1206]  8.29 8.47 180 top
R105  100K/4/5%  [R0402]  18.61 11.2 180 bottom
R106  100K/4/5%  [R0402]  18.61 10.31 0 bottom
R107  DNP  [R0402]  23.69 5.38 0 bottom
R108  DNP  [R0402]  16.63 5.41 180 bottom
R109  DNP  [R0402]  16.63 6.5 0 bottom
R110  DNP  [R0402]  23.19 6.27 180 bottom
R111  0R/4/5%  [R0402]  16.63 4.52 0 bottom
R112  0R/4/5%  [R0402]  23.69 4.5 180 bottom
R113  10K/4/5%  [R0402]  31.58 30.67 180 top
R114  22R/4/5%  [R0402]  34.69 24.92 270 top
R115  DNP  [R0402]  36.85 22.69 90 bottom
R116  0R/6/5%  [R0603]  41.63 13.74 180 top
R117  22R/4/5%  [R0402]  38.62 22.69 90 bottom
R118  22R/4/5%  [R0402]  36.98 25.35 0 top
R119  22R/4/5%  [R0402]  38.76 25.35 180 top
R120  10K/4/5%  [R0402]  37.73 22.69 90 bottom
R121  22R/4/5%  [R0402]  33.69 21.46 0 top
R122  22R/4/5%  [R0402]  33.69 19.68 0 top
R123  0R/6/5%  [R0603]  34.18 13.74 0 top
R124  1K/4/5%  [R0402]  38.52 13.48 90 top
R125  22R/4/5%  [R0402]  33.69 20.57 0 top
R126  22R/4/5%  [R0402]  33.69 18.8 0 top
R127  0R/6/5%  [R0603]  42.24 18.77 0 top
R128  0R/6/5%  [R0603]  42.72 25.21 90 bottom
R129  0R/6/5%  [R0603]  40.69 25.21 90 bottom
R130  2.2K/4/5%  [R0402]  40.96 21.62 0 bottom
R131  DNP  [R0402]  44.47 5.04 180 top
R132  0R/6/5%  [R0603]  37.98 15.77 180 bottom
R133  10K/4/5%  [R0402]  48.72 14.76 90 bottom
R134  22R/4/5%  [R0402]  54.24 12.88 270 bottom
R135  10K/4/5%  [R0402]  56.88 14.71 90 bottom
R136  22R/4/5%  [R0402]  62.58 13.3 0 bottom
R137  DNP  [R0402]  98.09 22.78 90 top
R138  1.5K/4/5%  [R0402]  97.2 22.78 90 top
R139  0R/4/5%  [R0402]  88.79 21.18 180 bottom
R140  0R/4/5%  [R0402]  88.79 23.18 180 bottom
R141  0R/4/5%  [R0402]  88.79 24.18 180 bottom
R142  0R/4/5%  [R0402]  88.79 25.18 180 bottom
R143  0R/4/5%  [R0402]  88.79 22.18 180 bottom
R144  0R/4/5%  [R0402]  88.79 20.18 180 bottom
R145  0R/4/5%  [R0402]  85.83 24.22 180 bottom
R146  22R/4/5%  [R0402]  89.26 27.07 90 bottom
R147  22R/4/5%  [R0402]  89.7 29.29 180 bottom
R148  22R/4/5%  [R0402]  88.81 30.18 180 bottom
R149  22R/4/5%  [R0402]  88.81 31.18 180 bottom
R150  22R/4/5%  [R0402]  88.81 32.18 180 bottom
R151  1K/4/5%  [R0402]  99.88 9.91 180 bottom
R152  1K/4/5%  [R0402]  101.2 12.11 180 bottom
R153  DNP  [R0402]  95.91 13.64 0 top
R154  10K/4/5%  [R0402]  91.76 16.8 270 bottom
R155  DNP  [R0402]  100.05 22.78 270 top
R156  0R/4/5%  [R0402]  91.81 20.12 90 bottom
R157  1K/4/5%  [R0402]  99.16 22.78 90 top
R158  2.49K/4/1%  [R0402]  99.7 11.91 90 top
R159  4.7K/4/5%  [R0402]  87.48 28.85 90 bottom
R160  4.7K/4/5%  [R0402]  87.48 27.07 90 bottom
R161  DNP  [R0402]  85.83 26 180 bottom
R162  DNP  [R0402]  93.73 12.89 90 bottom
R163  DNP  [R0402]  94.62 12.89 90 bottom
R164  DNP  [R0402]  96.66 12.89 90 bottom
R165  4.7K/4/5%  [R0402]  95.51 12.89 270 bottom
R166  4.7K/4/5%  [R0402]  97.54 12.89 270 bottom
R167  4.7K/4/5%  [R0402]  86.43 32.18 180 bottom
R168  4.7K/4/5%  [R0402]  86.43 31.18 180 bottom
R169  4.7K/4/5%  [R0402]  86.43 30.18 180 bottom
R170  DNP  [R0402]  88.37 28.85 270 bottom
R171  DNP  [R0402]  88.37 27.07 270 bottom
R172  4.7K/4/5%  [R0402]  85.83 25.11 0 bottom
R173  4.7K/4/5%  [R0402]  92.85 12.89 270 bottom
R174  DNP  [R0402]  97.84 42.44 90 top
R175  1.5K/4/5%  [R0402]  96.95 42.44 90 top
R176  0R/4/5%  [R0402]  88.79 43.18 180 bottom
R177  0R/4/5%  [R0402]  88.79 42.18 180 bottom
R178  0R/4/5%  [R0402]  88.79 40.18 180 bottom
R179  0R/4/5%  [R0402]  88.79 39.18 180 bottom
R180  0R/4/5%  [R0402]  88.79 38.18 180 bottom
R181  0R/4/5%  [R0402]  88.79 41.18 180 bottom
R182  22R/4/5%  [R0402]  85.96 45.85 90 bottom
R183  22R/4/5%  [R0402]  85.96 43.56 90 bottom
R184  22R/4/5%  [R0402]  88.57 50.84 90 bottom
R185  22R/4/5%  [R0402]  88.79 49.18 180 bottom
R186  22R/4/5%  [R0402]  88.79 48.18 180 bottom
R187  22R/4/5%  [R0402]  88.79 47.18 180 bottom
R188  1K/4/5%  [R0402]  101.99 26.54 180 bottom
R189  1K/4/5%  [R0402]  101.99 29.03 180 bottom
R190  10K/4/5%  [R0402]  91.58 36.27 270 bottom
R191  DNP  [R0402]  99.61 42.44 270 top
R192  DNP  [R0402]  95.91 33.27 0 top
R193  0R/4/5%  [R0402]  91.71 38.18 90 bottom
R194  1K/4/5%  [R0402]  98.73 42.44 90 top
R195  2.49K/4/1%  [R0402]  99.73 31.37 90 top
R196  4.7K/4/5%  [R0402]  86.8 50.84 90 bottom
R197  4.7K/4/5%  [R0402]  84.18 43.23 90 bottom
R198  4.7K/4/5%  [R0402]  84.18 45.85 90 bottom
R199  DNP  [R0402]  96.43 31.33 90 bottom
R200  DNP  [R0402]  97.32 31.33 90 bottom
R201  DNP  [R0402]  99.6 31.33 90 bottom
R202  4.7K/4/5%  [R0402]  98.21 31.33 270 bottom
R203  4.7K/4/5%  [R0402]  100.49 31.33 270 bottom
R204  4.7K/4/5%  [R0402]  86.12 47.18 180 bottom
R205  4.7K/4/5%  [R0402]  86.12 48.18 180 bottom
R206  4.7K/4/5%  [R0402]  86.12 49.18 180 bottom
R207  DNP  [R0402]  87.68 50.84 270 bottom
R208  DNP  [R0402]  85.07 43.56 270 bottom
R209  DNP  [R0402]  85.07 45.85 270 bottom
R210  4.7K/4/5%  [R0402]  95.54 31.33 270 bottom
R211  10K/4/5%  [R0402]  28.28 42.43 270 top
R212  10K/4/5%  [R0402]  28.9 53 180 bottom
R213  10K/4/5%  [R0402]  30.58 46.93 270 bottom
R214  10K/4/5%  [R0402]  31.62 59.41 0 top
R215  10K/4/5%  [R0402]  27.01 42.43 270 top
R216  DNP  [R0402]  74.47 53.17 270 bottom
R217  DNP  [R0402]  29.18 42.43 270 top
R218  22R/4/5%  [R0402]  28.9 49.4 180 bottom
R219  22R/4/5%  [R0402]  28.9 50.3 180 bottom
R220  100R/4/5%  [R0402]  29.78 51.2 0 bottom
R221  22R/4/5%  [R0402]  28.9 52.1 180 bottom
R222  0R/4/5%  [R0402]  28 51.2 0 bottom
R223  22R/4/5%  [R0402]  24.34 42.43 270 top
R224  22R/4/5%  [R0402]  26.12 42.43 270 top
R225  22R/4/5%  [R0402]  17.23 42.43 270 top
R226  22R/4/5%  [R0402]  18.12 42.43 270 top
R227  22R/4/5%  [R0402]  20.79 42.43 270 top
R228  22R/4/5%  [R0402]  22.56 42.43 270 top
R229  DNP  [R0402]  21.84 46.9 0 bottom
R230  DNP  [R0402]  21.84 48.68 0 bottom
R231  DNP  [R0402]  22.29 50.69 90 bottom
R232  DNP  [R0402]  24.38 48.78 180 bottom
R233  DNP  [R0402]  23.61 46.9 180 bottom
R234  0R/4/5%  [R0402]  31.62 58.52 0 top
R235  DNP  [R0402]  23.45 42.43 270 top
R236  10K/4/5%  [R0402]  25.23 42.43 270 top
R237  10K/4/5%  [R0402]  16.34 42.43 270 top
R238  10K/4/5%  [R0402]  19.01 42.43 270 top
R239  10K/4/5%  [R0402]  19.9 42.43 270 top
R240  10K/4/5%  [R0402]  21.68 42.43 270 top
R241  DNP  [R0402]  31.87 51.55 270 top
R242  DNP  [R0402]  31.87 50.67 90 bottom
R243  DNP  [R0402]  40.84 52.38 90 top
R244  DNP  [R0402]  31.87 53.33 270 top
R245  DNP  [R0402]  40.86 50.04 270 bottom
R246  DNP  [R0402]  31.87 48.9 90 bottom
R247  100K/4/5%  [R0402]  115.23 5.32 270 bottom
R248  10K/4/5%  [R0402]  42.41 55.92 90 bottom
R249  10K/4/5%  [R0402]  84.73 67.01 270 bottom
R250  470R/4/5%  [R0402]  106.19 4.31 90 bottom
R251  22R/4/5%  [R0402]  73.05 61.52 0 bottom
R252  22R/4/5%  [R0402]  84.76 61.62 180 bottom
R253  470R/4/5%  [R0402]  104.06 4.24 90 bottom
R254  470R/4/5%  [R0402]  41.53 46.69 180 bottom
R255  10K/4/5%  [R0402]  73.64 68.58 270 bottom
R256  DNP  [R0402]  72.75 68.58 270 bottom
R257  10K/4/5%  [R0402]  8.3 25.49 270 bottom
R258  22R/4/5%  [R0402]  9.07 18.75 270 bottom
R259  DNP  [R0402]  9.96 18.75 270 bottom
R260  22R/4/5%  [R0402]  9.19 25.49 270 bottom
R261  10K/4/5%  [R0402]  8.18 18.75 270 bottom
R262  DNP  [R0402]  10.08 25.49 270 bottom
R263  10K/4/5%  [R0402]  12.69 34.83 0 bottom
R264  22R/4/5%  [R0402]  12.59 32.67 0 bottom
R265  DNP  [R0402]  12.59 33.56 0 bottom
R266  22R/4/5%  [R0402]  12.69 35.71 0 bottom
R267  10K/4/5%  [R0402]  12.59 31.78 0 bottom
R268  DNP  [R0402]  12.19 37.1 90 bottom
R269  0.25R/12/1%  [R1206]  45.04 57.4 0 bottom
R270  1K/4/5%/DNP  [R0402]  100.11 59.65 270 top
REF  -  [unnamed#2]  4.06 12.85 90 top
REF#2  -  [unnamed#2]  4.06 11.58 270 bottom
S1  TS-1185 3*3.54* 2.5 250g  [KEY-3X4X2_5]  109.83 4.27 0 top
S2  TS-1185 3*3.54* 2.5 250g  [KEY-3X4X2_5]  115.43 4.27 0 top
SW1  218-4LPSTR  [SW-2X4]  96.73 4.88 90 top
T1  SMD  [TEST0_8-SMD]  29.55 37.31 0 top
T2  SMD  [TEST0_8-SMD]  16.48 36.92 270 top
T3  SMD  [TEST0_8-SMD]  28.66 35.1 0 top
T4  SMD  [TEST0_8-SMD]  16.48 35.75 90 top
T5  SMD  [TEST0_8-SMD]  87.52 58.93 180 top
T6  SMD  [TEST0_8-SMD]  84.65 18.57 270 bottom
T7  SMD  [TEST0_8-SMD]  84.65 17.17 180 bottom
T8  SMD  [TEST0_8-SMD]  106.65 47.6 180 top
T9  SMD  [TEST0_8-SMD]  31.54 52.88 90 bottom
T10  SMD  [TEST0_8-SMD]  20.54 52.22 270 bottom
T11  SMD  [TEST0_8-SMD]  18.46 51.21 0 bottom
T12  SMD  [TEST0_8-SMD]  16.46 52.16 180 bottom
T13  SMD  [TEST0_8-SMD]  11.98 52.04 270 bottom
T14  SMD  [TEST0_8-SMD]  97.46 24.42 270 top
T15  SMD  [TEST0_8-SMD]  95.22 24.73 270 top
T16  SMD  [TEST0_8-SMD]  97.58 44.03 270 top
T17  SMD  [TEST0_8-SMD]  93.82 44.21 270 top
T18  SMD  [TEST0_8-SMD]  91.58 45.73 270 top
T19  SMD  [TEST0_8-SMD]  73.19 62.76 180 bottom
T20  SMD  [TEST0_8-SMD]  62.84 11.94 180 bottom
T21  SMD  [TEST0_8-SMD]  61.41 11.43 180 bottom
T22  SMD  [TEST0_8-SMD]  92.33 50.18 0 top
TEMPLATE1  TEMPLATE_A2  [TEMPLATE-A2]  -52.4 -117.73 0 top
TP1  SMD  [HOLE-TP0_9S16]  26.24 14.83 90 top
TP2  SMD  [HOLE-TP0_9S16]  30.79 3.9 90 top
TP3  SMD  [HOLE-TP0_9S16]  43.05 37.55 90 top
TP4  SMD  [HOLE-TP0_9S16]  41.73 34.92 90 top
TP5  SMD  [HOLE-TP0_9S16]  102.38 44.42 90 top
TP6  SMD  [HOLE-TP0_9S16]  90.79 68.35 90 top
U1  MS-12D17G4  [SW-MS-12D17G4]  51.9 4.53 0 top
U2  CH224D  [QFN20-CH224D]  65.83 11.13 270 bottom
U3  SM8103ADC  [SOT23-6]  34.29 43.37 270 top
U4  RY3408  [TSOT23-5]  38.32 31.22 90 top
U5  PCMF2USB3S  [WLCSP10]  13.31 49.84 90 top
U6  PCMF3USB3S/CZ  [WLCSP15]  13.31 53.18 90 top
U7  RS0108YQ20  [TSSOP20]  22.55 34.39 0 top
U8  RS0102YVS8  [VSSOP8]  47.85 21.75 270 bottom
U9  STUSB1600AQTR  [QFN24]  82.19 12.6 0 bottom
U10  CH334H  [QFN28_CH334DS]  96.9 54.51 90 top
U11  LT8912B  [QFN64-0_4-LT8912B]  21.38 24.92 180 top
U12  PCMF2USB3S  [WLCSP10]  23.21 13.34 180 top
U13  PCMF2USB3S  [WLCSP10]  20.39 13.34 180 top
U14  RS0102YVS8  [VSSOP8]  20.04 5.26 180 bottom
U15  ES8388  [QFN28-0_45]  37.58 20.83 0 top
U16  YT8531SC  [QFN48-0_4]  94.76 17.76 180 top
U17  SR05-04A  [SOT23-6]  100.96 15.93 180 top
U18  SR05-04A  [SOT23-6]  100.96 19.53 180 top
U19  YT8531SC  [QFN48-0_4]  94.76 37.39 180 top
U20  SR05-04A  [SOT23-6]  100.96 35.56 180 top
U21  SR05-04A  [SOT23-6]  100.96 39.16 180 top
U22  BL-M8822CS1S  [MODULE-L297B-SR]  22.99 52.55 0 top
U23  SN74CBTLV3257PWR  [TSSOP16]  36.32 51.23 0 bottom
U24  SN74CBTLV3257PWR  [TSSOP16]  36.32 51.23 0 top
U25  RX-8025T/UC  [SOP14]  79.12 64.15 90 bottom
U26  MYC-YG2L  [MYB-YOUPK43X45_1_00-LGA58]  66.85 33.68 180 top
Y1  24MHz  [3225]  8.89 46.25 90 bottom
Y2  12MHz  [3225]  97.43 59.31 0 top
Y3  25MHz  [3225]  19.78 17.17 0 top
Y4  11.2896MHz  [3225]  32.2 27.94 270 top
Y5  11.2896MHz  [3225]  51.41 14.21 0 bottom
Y6  12.288MHz  [3225]  59.56 14.18 0 bottom
Y7  25MHz  [3225]  96.19 11.45 180 top
Y8  25MHz  [3225]  96.19 31.09 180 top
Y9  DNP  [3225]  24.96 51.19 0 bottom

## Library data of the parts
C1-C9 C12-C174 C176-C178 = Ceramic Capacitor
CT1 CT2 = Tantalum Capacitor
D1-D16 D18-D24 D27-D35 D37 D38 D43-D47 = TVS Diode
D17 = Schottky Diode
D25 D26 D36 = General Diode
D39 D41 = LED-17-21SURC/S530-A3/TR8
D40 = BAT54C
D42 = LED-19-217/BHC-ZL1M2RY/3T
F1-F3 = Fuse
FB1-FB15 = Ferrite Bead
J1 = USB616FC-C2014216
J2 = FPC24
J3 = UT12111-B1609-7F
J4 = UB11121-8FDE-4F
J5 = WQ21801-B2180-7F
J6 = FPC40
J7 = HDMI
J8 = Audio-704-06700003-A
J9 J10 = S11-ZZ-0319
J13 = 2X20PIN
J14 = 1X2PIN
J15 J16 = SIP3-DROIT
J17 J18 = U_1.FL-LP-040
L2 L3 L6 L7 = Inductor
L4 L5 = Common Choke
M1-M6 T1-T22 = TP
MTG1-MTG4 = MHOLE_3
MTG5 MTG6 = Mounting_Hole_1P
Q3 Q4 = P-MOSFET
Q5 = NPN Transistor
Q6-Q9 = N-MOSFET
R3-R6 R10-R12 R14 R19 R20 R28 R29 R36-R39 R53-R55 R59 R60 R62 R63 R68-R74 R77 R83 R85 R101 R102 R113 R116 R123 R124 R127-R130 R132 R133 R135 R138 R151 R152 R159 R160 R166-R169 R172 R173 R175 R188-R190 R196-R198 R203-R206 R210-R215 R236-R240 R249 R250 R253-R255 R257 R261 R263 R267 R269 R270 = Resister
R8 R15 R17 R40-R43 R47 R49 R52 R56 R67 R76 R78-R82 R86-R100 R103-R106 R111 R112 R120 R139-R145 R154 R156-R158 R176-R181 R193-R195 R220 R222 R234 = Resister: signal model: RESISTER_R0402_0R/4/5%_0R/4/5%
R9 R44 R58 R107 R108 R155 R174 R191 R192 R208 = RESISTER: signal model: RESISTER_R0402_0R/4/5%_0R/4/5%
R16 R18 R30-R33 R35 R45 R46 R48 R57 R61 R64-R66 R109 R110 R115 R131 R137 R153 R161 R170 R171 R207 R209 R216 R217 R229-R233 R235 R241-R246 R256 R259 R262 R265 R268 = RESISTER
R21 R23-R27 R34 R50 R51 R75 R84 R114 R117-R119 R121 R122 R125 R126 R146-R150 R165 R182-R187 R202 R218 R219 R221 R223-R228 R247 R248 R251 R252 = Resister: signal model: RESISTER_R0402_22R/4/5%_22R/4/5%
R134 R136 R258 R260 R264 R266 = Resister: signal model: RESISTER_R0402_22/4/5%_22/4/5%
R162-R164 R199-R201 = RESISTER: signal model: RESISTER_R0402_22R/4/5%_22R/4/5%
S1 S2 = KEY-TS-1109W
SW1 = SWITCH-218-4LPSTR
TEMPLATE1 = TEMPLATE-A2
TP1-TP6 = TP_7
U1 = MS-12D17G4
U2 = CH224D
U3 = SM8103ADC
U4 = RT8059GJ5
U5 U12 U13 = PCMF2USB3S
U6 = PCMF3USB3S
U7 = TXB0108
U8 U14 = TXS0102DCT
U9 = STUSB1600AQTR: signal model: PCMF2USB3S_WLCSP10_IC_PCMF2USB3_PCMF2USB3S
U10 = CH334H: signal model: PCMF2USB3S_WLCSP10_IC_PCMF2USB3_PCMF2USB3S
U11 = LT8912B
U15 = ES8388
U16 U19 = YT8521SH
U17 U18 U20 U21 = TPD4E1U06
U22 = FG6222BSRC-E0
U23 U24 = SN74CBTLV3257
U25 = RX-8025T
U26 = MYC-Y15X_0
Y1 Y4-Y6 Y9 = Oscillator_4P
Y2 Y3 = Crystal_4P
Y7 Y8 = Crystal_0

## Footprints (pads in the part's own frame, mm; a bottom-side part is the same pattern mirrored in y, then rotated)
3225
  oval 1.3x1 smd: 1(-1.15,-0.9) 2(1.15,-0.9) 3(1.15,0.9) 4(-1.15,0.9)
C0402
  custom 0.125x0.125 smd: 1(-0.44,0) 2(0.44,0)
C0603
  oval 0.9x0.9 smd: 1(-0.724,0) 2(0.724,0)
C1206
  oval 1x1.8 smd: 1(-1.45,0) 2(1.45,0)
CKX-704
  round 1.7 hole 1.7 unplated: (-3.5,0) (3.5,0)
  rect 1.2x2 smd: 2(-3.7,3.6) 3(3.3,3.6) 5(-3.7,-3.6) 6(-0.4,-3.6) 7(5.1,-3.6)
  rect 1.2x2.6 smd: 4(5.6,3.6)
CONN1X2-1_25-DIP
  rect 0.95x0.95 hole 0.6: 1(0.625,0)
  oval 0.85x0.95 hole 0.6: 2(-0.625,0)
CONN1X3-2_54-DIP
  rect 1.6x1.6 hole 0.9: 1(0,2.54)
  round 1.6 hole 0.9: 2(0,0) 3(0,-2.54)
CT3528-B
  oval 1.5x2.4 smd: 1(-1.65,0) 2(1.65,0)
D0402
  custom 0.125x0.125 smd: 1(-0.44,0) 2(0.44,0)
DO-214AA
  oval 2x2.3 smd: 1(-2.2,0) 2(2.2,0)
F1206
  oval 1.2x1.9 smd: 1(-1.497,0) 2(1.497,0)
FB0603
  oval 0.9x0.9 smd: 1(-0.75,0) 2(0.75,0)
FL_2D95X1D55_2SP
  rect 1.143x1.143 smd: 1(0,-1.6)
  rect 1.118x2.21 smd: 2(-1.5,0) 3(1.5,0)
FPC24-0_5-H
  oval 0.3x1.8 smd: 1(5.75,-0.2) 2(5.25,-0.2) 3(4.75,-0.2) 4(4.25,-0.2) 5(3.75,-0.2) 6(3.25,-0.2) 7(2.75,-0.2) 8(2.25,-0.2) 9(1.75,-0.2) 10(1.25,-0.2) 11(0.75,-0.2) 12(0.25,-0.2) 13(-0.25,-0.2) 14(-0.75,-0.2) 15(-1.25,-0.2) 16(-1.75,-0.2) 17(-2.25,-0.2) 18(-2.75,-0.2) 19(-3.25,-0.2) 20(-3.75,-0.2) 21(-4.25,-0.2) 22(-4.75,-0.2) 23(-5.25,-0.2) 24(-5.75,-0.2)
  rect 1.8x2.6 smd: 25(-8.05,-2.421) 26(8.05,-2.421)
FPC40-0_5-H
  oval 0.3x1.3 smd: 1(9.75,2.3) 2(9.25,2.3) 3(8.75,2.3) 4(8.25,2.3) 5(7.75,2.3) 6(7.25,2.3) 7(6.75,2.3) 8(6.25,2.3) 9(5.75,2.3) 10(5.25,2.3) 11(4.75,2.3) 12(4.25,2.3) 13(3.75,2.3) 14(3.25,2.3) 15(2.75,2.3) 16(2.25,2.3) 17(1.75,2.3) 18(1.25,2.3) 19(0.75,2.3) 20(0.25,2.3) 21(-0.25,2.3) 22(-0.75,2.3) 23(-1.25,2.3) 24(-1.75,2.3) 25(-2.25,2.3) 26(-2.75,2.3) 27(-3.25,2.3) 28(-3.75,2.3) 29(-4.25,2.3) 30(-4.75,2.3) 31(-5.25,2.3) 32(-5.75,2.3) 33(-6.25,2.3) 34(-6.75,2.3) 35(-7.25,2.3) 36(-7.75,2.3) 37(-8.25,2.3) 38(-8.75,2.3) 39(-9.25,2.3) 40(-9.75,2.3)
  rect 1.8x2.2 smd: 41(-11.45,-0.721) 42(11.45,-0.721)
HOLE3_2P-8
  round 0.85 hole 0.5: 1(1.605,1.605) 2(2.261,0) 3(1.6,-1.6) 4(0,-2.261) 5(-1.6,-1.6) 6(-2.261,0) 7(-1.595,1.595) 8(0,2.261)
  round 3.5 hole 3.2: 9(0,0)
HOLE-TP0_9S16
  rect 1.6x1.6 hole 0.9: 1(0,0)
ID-BOARD
  round 1.016 smd: 1(0,0)
INDCM-SDCW2012
  oval 1x0.5 smd: 1(-0.9,0.502) 2(0.9,0.502) 3(0.9,-0.502) 4(-0.9,-0.502)
KEY-3X4X2_5
  oval 1.3x0.9 smd: 1(1.925,-0.75) 2(-1.925,-0.75) 3(1.925,0.75) 4(-1.925,0.75)
L2X2_5
  oval 1.2x2 smd: 1(-1.1,0) 2(1.1,0)
L3X3
  oval 3x1.2 smd: 1(0,1.22) 2(0,-1.22)
L5_2X5_5
  oval 2.6x1.8 smd: 1(0,2.4) 2(0,-2.4)
LED0603
  oval 0.8x1 smd: 1(-0.85,0) 2(0.85,0)
LED0805
  oval 1.3x0.8 smd: 1(0,0.899) 2(0,-0.899)
MH236-125T
  round 5.994 hole 3.175: 1(0,0)
MODULE-L297B-SR
  oval 0.4x1.3 smd: 1(4.5,7.35) 2(3.6,7.35) 3(2.7,7.35) 4(1.8,7.35) 5(0.9,7.35) 6(0,7.35) 7(-0.9,7.35) 8(-1.8,7.35) 9(-2.7,7.35) 10(-3.6,7.35) 11(-4.5,7.35) 26(-4.5,-7.35) 27(-3.6,-7.35) 28(-2.7,-7.35) 29(-1.8,-7.35) 30(-0.9,-7.35) 31(0,-7.35) 32(0.9,-7.35) 33(1.8,-7.35) 34(2.7,-7.35) 35(3.6,-7.35) 36(4.5,-7.35)
  oval 1.3x0.4 smd: 12(-6.35,5.85) 13(-6.35,4.95) 14(-6.35,4.05) 15(-6.35,3.15) 16(-6.35,2.25) 17(-6.35,1.35) 18(-6.35,0.45) 19(-6.35,-0.45) 20(-6.35,-1.35) 21(-6.35,-2.25) 22(-6.35,-3.15) 23(-6.35,-4.05) 24(-6.35,-4.95) 25(-6.35,-5.85) 37(6.35,-5.85) 38(6.35,-4.95) 39(6.35,-4.05) 40(6.35,-3.15) 41(6.35,-2.25) 42(6.35,-1.35) 43(6.35,-0.45) 44(6.35,0.45) 45(6.35,1.35) 46(6.35,2.25) 47(6.35,3.15) 48(6.35,4.05) 49(6.35,4.95) 50(6.35,5.85)
MYB-YOUPK43X45_1_00-LGA58
  oval 1.171x0.6 smd: 1(-21.5,20.5) 2(-21.5,19.5) 3(-21.5,18.5) 4(-21.5,17.5) 5(-21.5,16.5) 6(-21.5,15.5) 7(-21.5,14.5) 8(-21.5,13.5) 9(-21.5,12.5) 10(-21.5,11.5) 11(-21.5,10.5) 12(-21.5,9.5) 13(-21.5,8.5) 14(-21.5,7.5) 15(-21.5,6.5) 16(-21.5,5.5) 17(-21.5,4.5) 18(-21.5,3.5) 19(-21.5,2.5) 20(-21.5,1.5) 21(-21.5,0.5) 22(-21.5,-0.5) 23(-21.5,-1.5) 24(-21.5,-2.5) 25(-21.5,-3.5) 26(-21.5,-4.5) 27(-21.5,-5.5) 28(-21.5,-6.5) 29(-21.5,-7.5) 30(-21.5,-8.5) 31(-21.5,-9.5) 32(-21.5,-10.5) 33(-21.5,-11.5) 34(-21.5,-12.5) 35(-21.5,-13.5) 36(-21.5,-14.5) 37(-21.5,-15.5) 38(-21.5,-16.5) 39(-21.5,-17.5) 40(-21.5,-18.5) 41(-21.5,-19.5) 42(-21.5,-20.5) 83(21.5,-20.5) 84(21.5,-19.5) 85(21.5,-18.5) 86(21.5,-17.5) 87(21.5,-16.5) 88(21.5,-15.5) 89(21.5,-14.5) 90(21.5,-13.5) 91(21.5,-12.5) 92(21.5,-11.5) 93(21.5,-10.5) 94(21.5,-9.5) 95(21.5,-8.5) 96(21.5,-7.5) 97(21.5,-6.5) 98(21.5,-5.5) 99(21.5,-4.5) 100(21.5,-3.5) 101(21.5,-2.5) 102(21.5,-1.5) 103(21.5,-0.5) 104(21.5,0.5) 105(21.5,1.5) 106(21.5,2.5) 107(21.5,3.5) 108(21.5,4.5) 109(21.5,5.5) 110(21.5,6.5) 111(21.5,7.5) 112(21.5,8.5) 113(21.5,9.5) 114(21.5,10.5) 115(21.5,11.5) 116(21.5,12.5) 117(21.5,13.5) 118(21.5,14.5) 119(21.5,15.5) 120(21.5,16.5) 121(21.5,17.5) 122(21.5,18.5) 123(21.5,19.5) 124(21.5,20.5)
  oval 0.6x1.171 smd: 43(-19.5,-22.5) 44(-18.5,-22.5) 45(-17.5,-22.5) 46(-16.5,-22.5) 47(-15.5,-22.5) 48(-14.5,-22.5) 49(-13.5,-22.5) 50(-12.5,-22.5) 51(-11.5,-22.5) 52(-10.5,-22.5) 53(-9.5,-22.5) 54(-8.5,-22.5) 55(-7.5,-22.5) 56(-6.5,-22.5) 57(-5.5,-22.5) 58(-4.5,-22.5) 59(-3.5,-22.5) 60(-2.5,-22.5) 61(-1.5,-22.5) 62(-0.5,-22.5) 63(0.5,-22.5) 64(1.5,-22.5) 65(2.5,-22.5) 66(3.5,-22.5) 67(4.5,-22.5) 68(5.5,-22.5) 69(6.5,-22.5) 70(7.5,-22.5) 71(8.5,-22.5) 72(9.5,-22.5) 73(10.5,-22.5) 74(11.5,-22.5) 75(12.5,-22.5) 76(13.5,-22.5) 77(14.5,-22.5) 78(15.5,-22.5) 79(16.5,-22.5) 80(17.5,-22.5) 81(18.5,-22.5) 82(19.5,-22.5) 125(19.5,22.5) 126(18.5,22.5) 127(17.5,22.5) 128(16.5,22.5) 129(15.5,22.5) 130(14.5,22.5) 131(13.5,22.5) 132(12.5,22.5) 133(11.5,22.5) 134(10.5,22.5) 135(9.5,22.5) 136(8.5,22.5) 137(7.5,22.5) 138(6.5,22.5) 139(5.5,22.5) 140(4.5,22.5) 141(3.5,22.5) 142(2.5,22.5) 143(1.5,22.5) 144(0.5,22.5) 145(-0.5,22.5) 146(-1.5,22.5) 147(-2.5,22.5) 148(-3.5,22.5) 149(-4.5,22.5) 150(-5.5,22.5) 151(-6.5,22.5) 152(-7.5,22.5) 153(-8.5,22.5) 154(-9.5,22.5) 155(-10.5,22.5) 156(-11.5,22.5) 157(-12.5,22.5) 158(-13.5,22.5) 159(-14.5,22.5) 160(-15.5,22.5) 161(-16.5,22.5) 162(-17.5,22.5) 163(-18.5,22.5) 164(-19.5,22.5)
  round 1 smd: L1(-17.78,19.05) L2(-17.78,16.51) L3(-17.78,13.97) L4(-17.78,11.43) L5(-17.78,8.89) L6(-17.78,6.35) L7(-17.78,3.81) L8(-17.78,1.27) L9(-17.78,-1.27) L10(-17.78,-3.81) L11(-17.78,-6.35) L12(-17.78,-8.89) L13(-17.78,-11.43) L14(-17.78,-13.97) L15(-17.78,-16.51) L16(-17.78,-19.05) L17(-15.24,-19.05) L18(-12.7,-19.05) L19(-10.16,-19.05) L20(-7.62,-19.05) L21(-5.08,-19.05) L22(-2.54,-19.05) L23(0,-19.05) L24(2.54,-19.05) L25(5.08,-19.05) L26(7.62,-19.05) L27(10.16,-19.05) L28(12.7,-19.05) L29(15.24,-19.05) L30(17.78,-19.05) L31(17.78,-16.51) L32(17.78,-13.97) L33(17.78,-11.43) L34(17.78,-8.89) L35(17.78,-6.35) L36(17.78,-3.81) L37(17.78,-1.27) L38(17.78,1.27) L39(17.78,3.81) L40(17.78,6.35) L41(17.78,8.89) L42(17.78,11.43) L43(17.78,13.97) L44(17.78,16.51) L45(17.78,19.05) L46(15.24,19.05) L47(12.7,19.05) L48(10.16,19.05) L49(7.62,19.05) L50(5.08,19.05) L51(2.54,19.05) L52(0,19.05) L53(-2.54,19.05) L54(-5.08,19.05) L55(-7.62,19.05) L56(-10.16,19.05) L57(-12.7,19.05) L58(-15.24,19.05)
QFN20-CH224D
  oval 0.2x0.7 smd: 1(-0.8,-1.45) 2(-0.4,-1.45) 3(0,-1.45) 4(0.4,-1.45) 5(0.8,-1.45) 11(0.8,1.45) 12(0.4,1.45) 13(0,1.45) 14(-0.4,1.45) 15(-0.8,1.45)
  oval 0.7x0.2 smd: 6(1.45,-0.8) 7(1.45,-0.4) 8(1.45,0) 9(1.45,0.4) 10(1.45,0.8) 16(-1.45,0.8) 17(-1.45,0.4) 18(-1.45,0) 19(-1.45,-0.4) 20(-1.45,-0.8)
  rect 1.7x1.7 smd: 21(0,0)
QFN24
  oval 0.65x0.25 smd: 1(-1.9,1.25) 2(-1.9,0.75) 3(-1.9,0.25) 4(-1.9,-0.25) 5(-1.9,-0.75) 6(-1.9,-1.25) 13(1.9,-1.25) 14(1.9,-0.75) 15(1.9,-0.25) 16(1.9,0.25) 17(1.9,0.75) 18(1.9,1.25)
  oval 0.25x0.65 smd: 7(-1.25,-1.9) 8(-0.75,-1.9) 9(-0.25,-1.9) 10(0.25,-1.9) 11(0.75,-1.9) 12(1.25,-1.9) 19(1.25,1.9) 20(0.75,1.9) 21(0.25,1.9) 22(-0.25,1.9) 23(-0.75,1.9) 24(-1.25,1.9)
  rect 2.4x2.4 smd: 25(0,0)
QFN28-0_45
  oval 0.6x0.25 smd: 1(-1.9,1.35) 2(-1.9,0.9) 3(-1.9,0.45) 4(-1.9,0) 5(-1.9,-0.45) 6(-1.9,-0.9) 7(-1.9,-1.35) 15(1.9,-1.35) 16(1.9,-0.9) 17(1.9,-0.45) 18(1.9,0) 19(1.9,0.45) 20(1.9,0.9) 21(1.9,1.35)
  oval 0.25x0.6 smd: 8(-1.35,-1.9) 9(-0.9,-1.9) 10(-0.45,-1.9) 11(0,-1.9) 12(0.45,-1.9) 13(0.9,-1.9) 14(1.35,-1.9) 22(1.35,1.9) 23(0.9,1.9) 24(0.45,1.9) 25(0,1.9) 26(-0.45,1.9) 27(-0.9,1.9) 28(-1.35,1.9)
  rect 2.5x2.5 smd: 29(0,0)
QFN28_CH334DS
  oval 0.25x0.7 smd: 1(-1.5,-2.45) 2(-1,-2.45) 3(-0.5,-2.45) 4(0,-2.45) 5(0.5,-2.45) 6(1,-2.45) 7(1.5,-2.45) 15(1.5,2.45) 16(1,2.45) 17(0.5,2.45) 18(0,2.45) 19(-0.5,2.45) 20(-1,2.45) 21(-1.5,2.45)
  oval 0.7x0.25 smd: 8(2.45,-1.5) 9(2.45,-1) 10(2.45,-0.5) 11(2.45,0) 12(2.45,0.5) 13(2.45,1) 14(2.45,1.5) 22(-2.45,1.5) 23(-2.45,1) 24(-2.45,0.5) 25(-2.45,0) 26(-2.45,-0.5) 27(-2.45,-1) 28(-2.45,-1.5)
  rect 3.5x3.5 smd: 29(0,0)
QFN48-0_4
  oval 0.8x0.2 smd: 1(-3,2.2) 2(-3,1.8) 3(-3,1.4) 4(-3,1) 5(-3,0.6) 6(-3,0.2) 7(-3,-0.2) 8(-3,-0.6) 9(-3,-1) 10(-3,-1.4) 11(-3,-1.8) 12(-3,-2.2) 25(3,-2.2) 26(3,-1.8) 27(3,-1.4) 28(3,-1) 29(3,-0.6) 30(3,-0.2) 31(3,0.2) 32(3,0.6) 33(3,1) 34(3,1.4) 35(3,1.8) 36(3,2.2)
  oval 0.2x0.8 smd: 13(-2.2,-3) 14(-1.8,-3) 15(-1.4,-3) 16(-1,-3) 17(-0.6,-3) 18(-0.2,-3) 19(0.2,-3) 20(0.6,-3) 21(1,-3) 22(1.4,-3) 23(1.8,-3) 24(2.2,-3) 37(2.2,3) 38(1.8,3) 39(1.4,3) 40(1,3) 41(0.6,3) 42(0.2,3) 43(-0.2,3) 44(-0.6,3) 45(-1,3) 46(-1.4,3) 47(-1.8,3) 48(-2.2,3)
  custom 1.075x1.075 smd: 49(-0.1,-0.1)
QFN64-0_4-LT8912B
  oval 0.8x0.2 smd: 1(-3.75,3) 2(-3.75,2.6) 3(-3.75,2.2) 4(-3.75,1.8) 5(-3.75,1.4) 6(-3.75,1) 7(-3.75,0.6) 8(-3.75,0.2) 9(-3.75,-0.2) 10(-3.75,-0.6) 11(-3.75,-1) 12(-3.75,-1.4) 13(-3.75,-1.8) 14(-3.75,-2.2) 15(-3.75,-2.6) 16(-3.75,-3) 33(3.75,-3) 34(3.75,-2.6) 35(3.75,-2.2) 36(3.75,-1.8) 37(3.75,-1.4) 38(3.75,-1) 39(3.75,-0.6) 40(3.75,-0.2) 41(3.75,0.2) 42(3.75,0.6) 43(3.75,1) 44(3.75,1.4) 45(3.75,1.8) 46(3.75,2.2) 47(3.75,2.6) 48(3.75,3)
  oval 0.2x0.8 smd: 17(-3,-3.75) 18(-2.6,-3.75) 19(-2.2,-3.75) 20(-1.8,-3.75) 21(-1.4,-3.75) 22(-1,-3.75) 23(-0.6,-3.75) 24(-0.2,-3.75) 25(0.2,-3.75) 26(0.6,-3.75) 27(1,-3.75) 28(1.4,-3.75) 29(1.8,-3.75) 30(2.2,-3.75) 31(2.6,-3.75) 32(3,-3.75) 49(3,3.75) 50(2.6,3.75) 51(2.2,3.75) 52(1.8,3.75) 53(1.4,3.75) 54(1,3.75) 55(0.6,3.75) 56(0.2,3.75) 57(-0.2,3.75) 58(-0.6,3.75) 59(-1,3.75) 60(-1.4,3.75) 61(-1.8,3.75) 62(-2.2,3.75) 63(-2.6,3.75) 64(-3,3.75)
  rect 5.6x5.6 smd: 65(0,0)
QJ51191-LFB4
  oval 0.28x2.6 smd: 1(4.5,3.74) 2(4,3.74) 3(3.5,3.74) 4(3,3.74) 5(2.5,3.74) 6(2,3.74) 7(1.5,3.74) 8(1,3.74) 9(0.5,3.74) 10(0,3.74) 11(-0.5,3.74) 12(-1,3.74) 13(-1.5,3.74) 14(-2,3.74) 15(-2.5,3.74) 16(-3,3.74) 17(-3.5,3.74) 18(-4,3.74) 19(-4.5,3.74)
  oval 1.6x3.4 hole 1x2.7: 20(-7.25,2.98) 23(7.25,2.98)
  oval 1.6x2.8 hole 1x2.1: 21(-7.25,-2.98) 22(7.25,-2.98)
R0402
  custom 0.125x0.125 smd: 1(-0.44,0) 2(0.44,0)
R0603
  oval 0.9x0.9 smd: 1(-0.724,0) 2(0.724,0)
R1206
  oval 1x1.65 smd: 1(-1.3,0) 2(1.3,0)
S11-ZZ-0319
  round 3.25 hole 3.25: (-5.715,0) (5.715,0)
  round 1.8 hole 0.9: 1(-5.715,8.89) 2(-4.445,6.35) 3(-3.175,8.89) 4(-1.905,6.35) 5(-0.635,8.89) 6(0.635,6.35) 7(1.905,8.89) 8(3.175,6.35) 9(4.445,8.89) 10(5.715,6.35) 11(6.325,-3.38) 12(3.785,-4.9) 13(-3.785,-3.38) 14(-6.325,-4.9)
  oval 2x2.6 hole 1x1.6: 15(7.775,3.05) 16(-7.775,3.05)
SOD123
  oval 1.2x1 smd: 1(-1.5,0) 2(1.5,0)
SOD323
  oval 0.9x0.7 smd: 1(1.07,0) 2(-1.07,0)
SOP14
  oval 0.6x1.8 smd: 1(-3.81,-3.355) 2(-2.54,-3.355) 3(-1.27,-3.355) 4(0,-3.355) 5(1.27,-3.355) 6(2.54,-3.355) 7(3.81,-3.355) 8(3.81,3.355) 9(2.54,3.355) 10(1.27,3.355) 11(0,3.355) 12(-1.27,3.355) 13(-2.54,3.355) 14(-3.81,3.355)
SOT23-6
  oval 1.3x0.5 smd: 1(-1.2,0.95) 2(-1.2,0) 3(-1.2,-0.95) 4(1.2,-0.95) 5(1.2,0) 6(1.2,0.95)
SOT-23
  oval 0.95x1.2 smd: 1(-0.966,-0.993) 2(0.966,-0.993) 3(0,0.893)
SW-2X4
  oval 0.8x1.8 smd: 1(-1.91,-4.01) 2(-0.63,-4.01) 3(0.63,-4.01) 4(1.91,-4.01) 5(1.91,4.01) 6(0.63,4.01) 7(-0.63,4.01) 8(-1.91,4.01)
SW-MS-12D17G4
  oval 0.8x2.6 smd: 1(-2.5,-2.6) 2(0,2.6) 3(2.5,-2.6)
TEMPLATE-A2
  round 0 smd: 1(393.7,-5.08)
TEST0_8-SMD
  round 0.8 smd: 1(0,0)
TSM-2D54-2X20P
  round 1.8 hole 1.8 unplated: (-22.86,0) (22.86,0)
  oval 1.02x3.12 smd: 1(-24.12,-2.69) 2(-24.13,2.69) 3(-21.58,-2.69) 4(-21.59,2.69) 5(-19.04,-2.69) 6(-19.05,2.69) 7(-16.5,-2.69) 8(-16.51,2.69) 9(-13.96,-2.69) 10(-13.97,2.69) 11(-11.42,-2.69) 12(-11.42,2.69) 13(-8.88,-2.69) 14(-8.88,2.69) 15(-6.34,-2.69) 16(-6.34,2.69) 17(-3.8,-2.69) 18(-3.8,2.69) 19(-1.26,-2.69) 20(-1.26,2.69) 21(1.28,-2.69) 22(1.28,2.69) 23(3.82,-2.69) 24(3.82,2.69) 25(6.36,-2.69) 26(6.36,2.69) 27(8.9,-2.69) 28(8.9,2.69) 29(11.44,-2.69) 30(11.44,2.69) 31(13.98,-2.69) 32(13.98,2.69) 33(16.52,-2.69) 34(16.52,2.69) 35(19.06,-2.69) 36(19.06,2.69) 37(21.6,-2.69) 38(21.6,2.69) 39(24.14,-2.69) 40(24.14,2.69)
TSOT23-5
  oval 1.2x0.5 smd: 1(-1.35,1) 2(-1.35,0) 3(-1.35,-1) 4(1.35,-1) 5(1.35,1)
